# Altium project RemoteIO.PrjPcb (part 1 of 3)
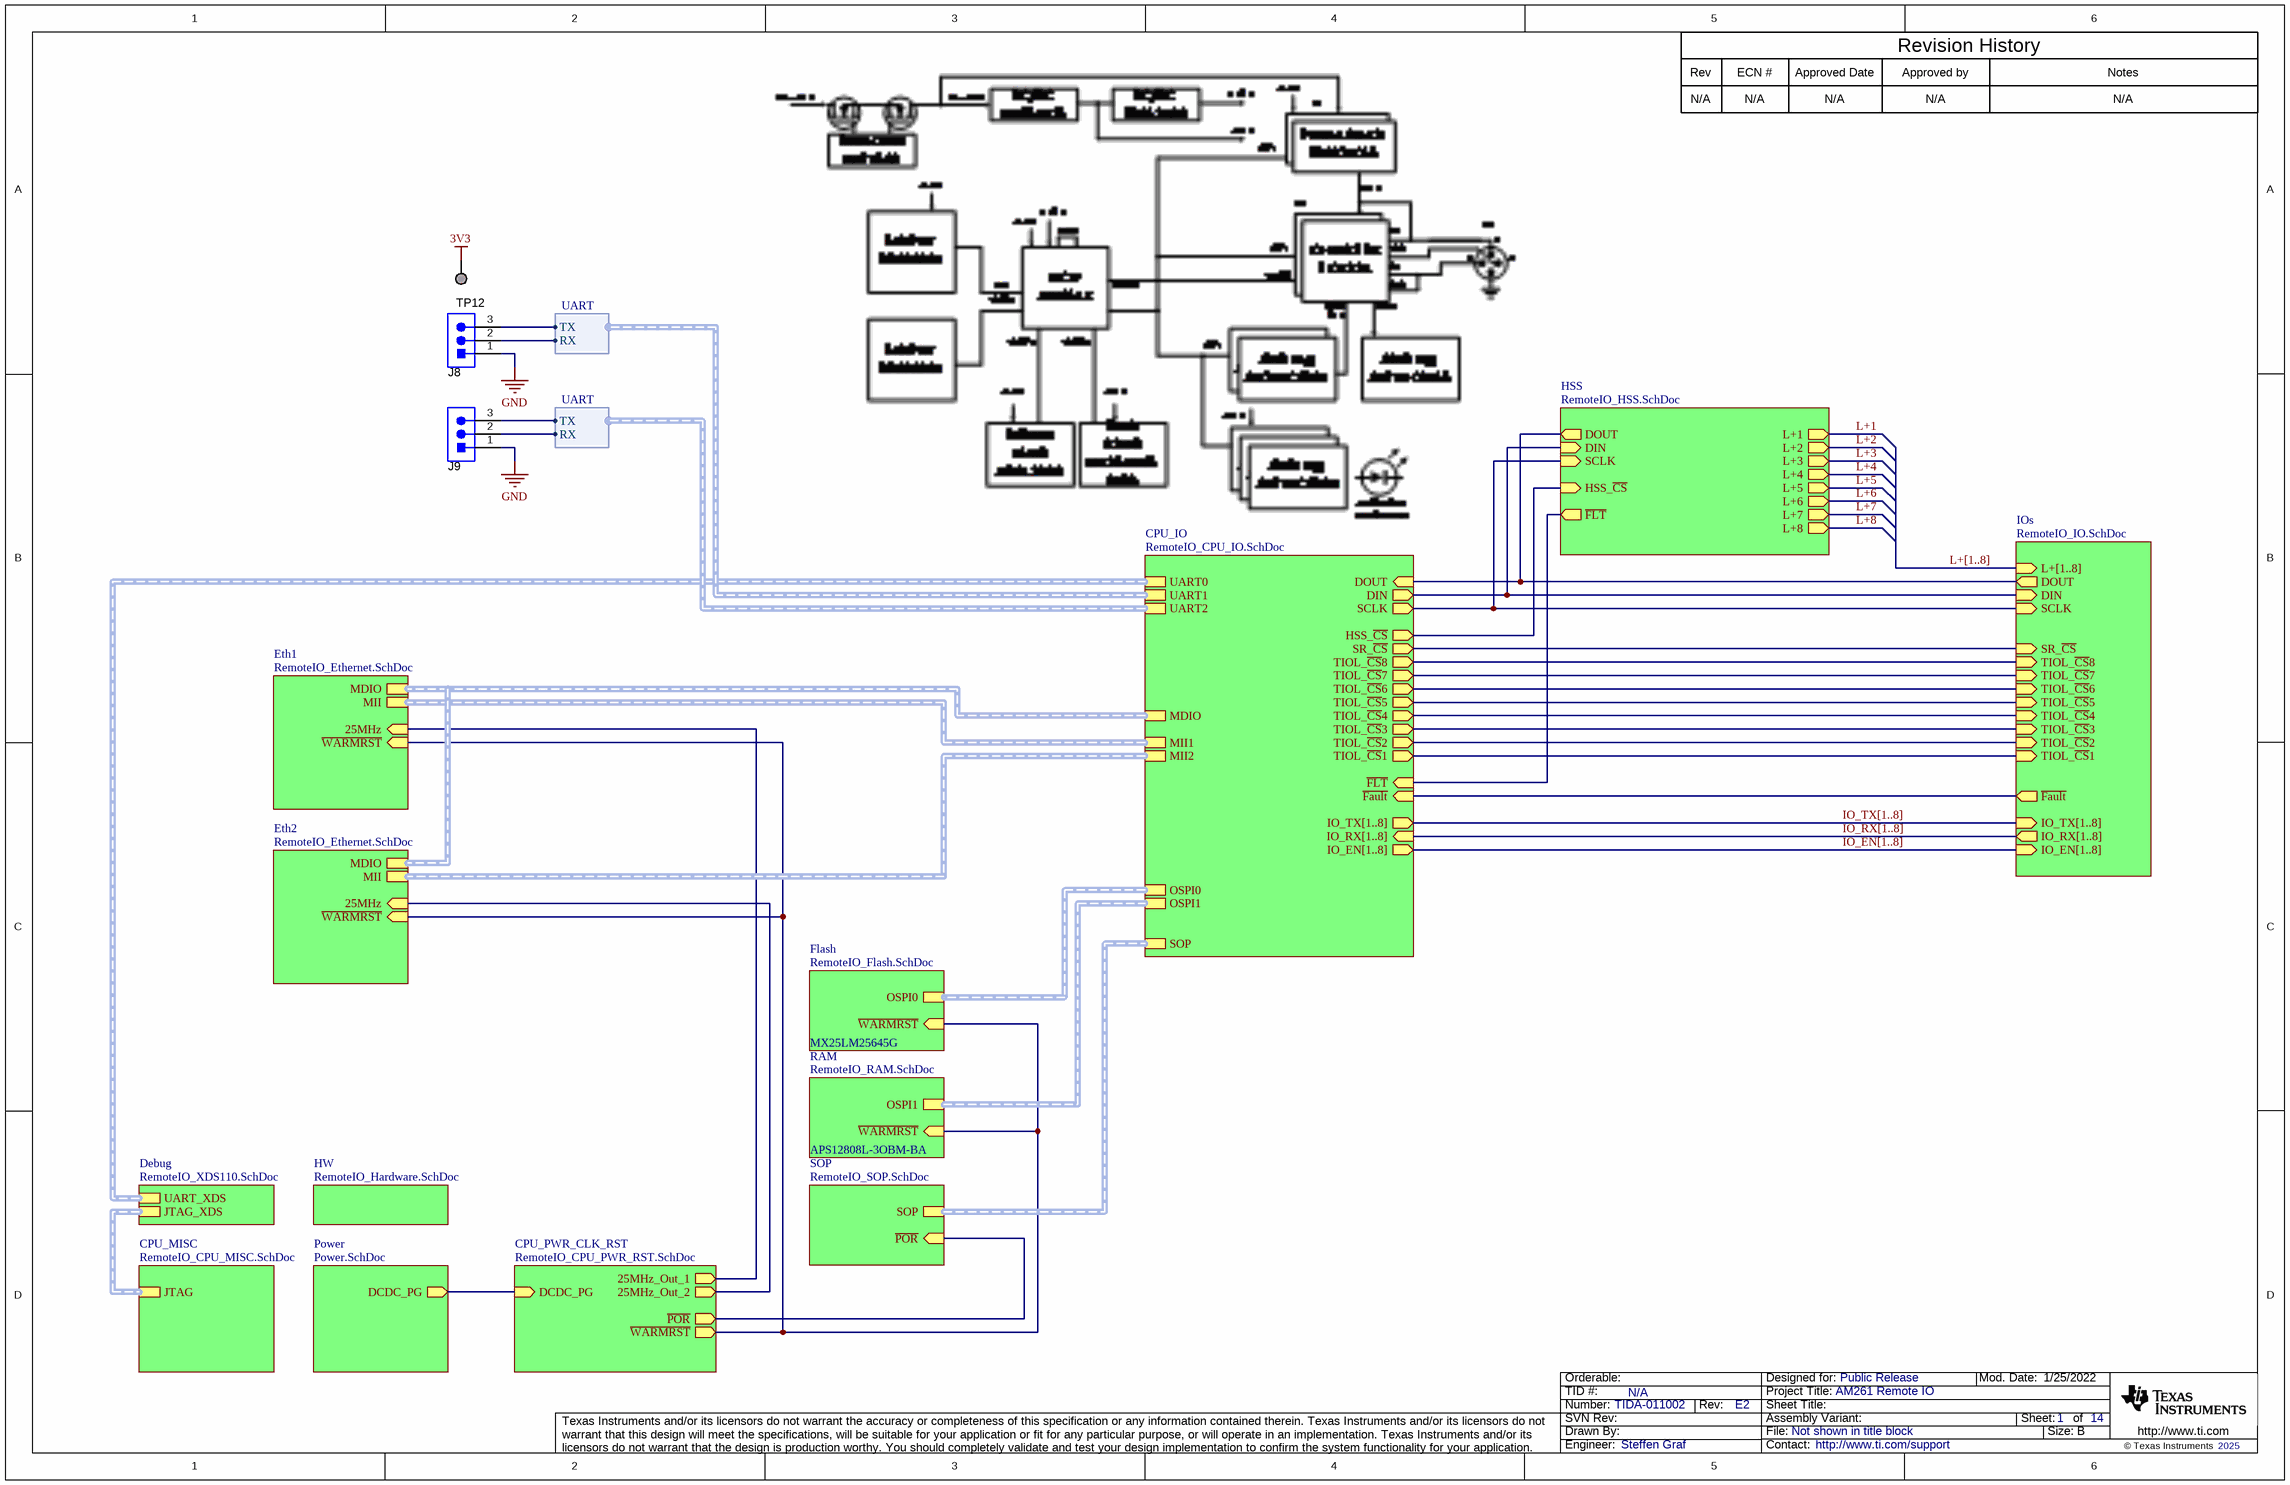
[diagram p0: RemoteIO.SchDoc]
TID: N/A; TechSupport: http://www.ti.com/support; SCH_Rev: E2; PRJ_Title: AM261 Remote IO; PRJ_Number: TIDA-011002; PRJ_Engineer: Steffen Graf; PRJ_Customer: Public Release; PCB_Rev: E2; PCB_Layout: Steffen Graf; CopyrightYear: 2025
14 sheets, 687 parts. Net scope: hierarchical (ports join the sheet entries above them; power ports are global).
Board file: RemoteIO.PcbDoc
Sheets:
  RemoteIO.SchDoc
    Power = Power.SchDoc
    Eth1 = RemoteIO_Ethernet.SchDoc
    Eth2 = RemoteIO_Ethernet.SchDoc
    CPU_IO = RemoteIO_CPU_IO.SchDoc
    IOs = RemoteIO_IO.SchDoc
      IO1 = RemoteIO_IOLinkPort.SchDoc
      IO2 = RemoteIO_IOLinkPort.SchDoc
      IO3 = RemoteIO_IOLinkPort.SchDoc
      IO4 = RemoteIO_IOLinkPort.SchDoc
      IO5 = RemoteIO_IOLinkPort.SchDoc
      IO6 = RemoteIO_IOLinkPort.SchDoc
      IO7 = RemoteIO_IOLinkPort.SchDoc
      IO8 = RemoteIO_IOLinkPort.SchDoc
    HW = RemoteIO_Hardware.SchDoc
    HSS = RemoteIO_HSS.SchDoc
    Flash = RemoteIO_Flash.SchDoc
    RAM = RemoteIO_RAM.SchDoc
    SOP = RemoteIO_SOP.SchDoc
    CPU_PWR_CLK_RST = RemoteIO_CPU_PWR_RST.SchDoc
    CPU_MISC = RemoteIO_CPU_MISC.SchDoc
    Debug = RemoteIO_XDS110.SchDoc

## Sheet RemoteIO.SchDoc
size 431 x 279 mm; Date: Not shown in title block; ApprovedBy: Not shown in title block; CheckedBy: Not shown in title block; Author: Not shown in title block; CompanyName: Not shown in title block; Engineer: Not shown in title block; Organization: Not shown in title block; Address1: Not shown in title block; Address2: Not shown in title block; Address3: Not shown in title block; Address4: Not shown in title block; DocumentNumber: 1; Revision: Use project parameter SCH_Rev; SheetNumber: 1; SheetTotal: 14; PageSetup: Record=PageOptions¦CenterHorizontal=True¦CenterVertical=True¦PrintScale=1.00¦XCorrection=1.00¦YCorrection=1.00¦PrintKind=0¦BorderSize=5000000¦LeftOffset=0¦BottomOffset=0¦Orientation=2¦PaperLength=1000¦PaperWidth=1000¦Scale=100¦PaperSource=15¦PrintQuality=600¦MediaType=1¦DitherType=10¦PaperKind=Letter¦PrintScaleMode=1

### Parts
J8  61300311121  [WURTH_61300311121]  (value not drawn)
J9  61300311121  [WURTH_61300311121]  (value not drawn)
TP12  TESTPOINT  [TP_50MIL-25MILHOLE]  (value not drawn)  (no BOM)

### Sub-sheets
CPU_IO = RemoteIO_CPU_IO.SchDoc: DOUT (in), DIN (out), SCLK (out), HSS_~{CS} (out), SR_~{CS} (out), TIOL_~{CS}8 (out), TIOL_~{CS}7 (out), TIOL_~{CS}6 (out), TIOL_~{CS}5 (out), TIOL_~{CS}4 (out), TIOL_~{CS}3 (out), TIOL_~{CS}2 (out), TIOL_~{CS}1 (out), ~{FLT} (in), ~{Fault} (in), IO_TX[1..8] (out), IO_RX[1..8] (in), IO_EN[1..8] (out), MII1 (harness MII), MII2 (harness MII), MDIO (harness MDIO), UART0 (harness UART), UART1 (harness UART), OSPI0 (harness OSPI), OSPI1 (harness OSPI), SOP (harness SOP), UART2 (harness UART)
CPU_MISC = RemoteIO_CPU_MISC.SchDoc: JTAG (harness JTAG)
CPU_PWR_CLK_RST = RemoteIO_CPU_PWR_RST.SchDoc: DCDC_PG (in), ~{POR} (out), ~{WARMRST} (out), 25MHz_Out_1 (out), 25MHz_Out_2 (out)
Debug = RemoteIO_XDS110.SchDoc: JTAG_XDS (harness JTAG), UART_XDS (harness UART)
Eth1 = RemoteIO_Ethernet.SchDoc: MII, MDIO, 25MHz (in), ~{WARMRST} (in)
Eth2 = RemoteIO_Ethernet.SchDoc: MII, MDIO, 25MHz (in), ~{WARMRST} (in)
Flash = RemoteIO_Flash.SchDoc: OSPI0 (harness OSPI), ~{WARMRST} (in)
HSS = RemoteIO_HSS.SchDoc: L+1 (out), L+2 (out), L+3 (out), L+4 (out), L+5 (out), L+6 (out), L+7 (out), L+8 (out), HSS_~{CS} (in), SCLK (in), DIN (in), DOUT (out), ~{FLT} (out)
HW = RemoteIO_Hardware.SchDoc: no entries
IOs = RemoteIO_IO.SchDoc: SR_~{CS} (in), ~{Fault} (out), TIOL_~{CS}8 (in), TIOL_~{CS}7 (in), TIOL_~{CS}6 (in), TIOL_~{CS}5 (in), TIOL_~{CS}4 (in), TIOL_~{CS}3 (in), TIOL_~{CS}2 (in), TIOL_~{CS}1 (in), SCLK (in), DIN (in), DOUT (out), L+[1..8] (in), IO_RX[1..8] (out), IO_TX[1..8] (in), IO_EN[1..8] (in)
Power = Power.SchDoc: DCDC_PG (out)
RAM = RemoteIO_RAM.SchDoc: OSPI1, ~{WARMRST} (in)
SOP = RemoteIO_SOP.SchDoc: SOP (harness SOP), ~{POR} (in)

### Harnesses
UART: TX, RX

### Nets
3V3: TP12.1
GND: J8.1 J9.1
25MHz: sheet Eth1/25MHz, sheet CPU_PWR_CLK_RST/25MHz_Out_1
25MHz: sheet Eth2/25MHz, sheet CPU_PWR_CLK_RST/25MHz_Out_2  [a separate net that carries the same name]
~{Fault}: sheet CPU_IO/~{Fault}, sheet IOs/~{Fault}
~{FLT}: sheet CPU_IO/~{FLT}, sheet HSS/~{FLT}
~{POR}: sheet SOP/~{POR}, sheet CPU_PWR_CLK_RST/~{POR}
~{WARMRST}: sheet Eth1/~{WARMRST}, sheet Eth2/~{WARMRST}, sheet Flash/~{WARMRST}, sheet RAM/~{WARMRST}, sheet CPU_PWR_CLK_RST/~{WARMRST}
CS1: sheet CPU_IO/TIOL_~{CS}1, sheet IOs/TIOL_~{CS}1
CS2: sheet CPU_IO/TIOL_~{CS}2, sheet IOs/TIOL_~{CS}2
CS3: sheet CPU_IO/TIOL_~{CS}3, sheet IOs/TIOL_~{CS}3
CS4: sheet CPU_IO/TIOL_~{CS}4, sheet IOs/TIOL_~{CS}4
CS5: sheet CPU_IO/TIOL_~{CS}5, sheet IOs/TIOL_~{CS}5
CS6: sheet CPU_IO/TIOL_~{CS}6, sheet IOs/TIOL_~{CS}6
CS7: sheet CPU_IO/TIOL_~{CS}7, sheet IOs/TIOL_~{CS}7
CS8: sheet CPU_IO/TIOL_~{CS}8, sheet IOs/TIOL_~{CS}8
DCDC_PG: sheet Power/DCDC_PG, sheet CPU_PWR_CLK_RST/DCDC_PG
DIN: sheet CPU_IO/DIN, sheet IOs/DIN, sheet HSS/DIN
DOUT: sheet CPU_IO/DOUT, sheet IOs/DOUT, sheet HSS/DOUT
HSS_~{CS}: sheet CPU_IO/HSS_~{CS}, sheet HSS/HSS_~{CS}
SCLK: sheet CPU_IO/SCLK, sheet IOs/SCLK, sheet HSS/SCLK
SR_~{CS}: sheet CPU_IO/SR_~{CS}, sheet IOs/SR_~{CS}
UART1_RX: J8.2 ; sheet CPU_IO/UART1.RX
UART1_TX: J8.3 ; sheet CPU_IO/UART1.TX
NetJ9_2: J9.2 ; sheet CPU_IO/UART2.RX
NetJ9_3: J9.3 ; sheet CPU_IO/UART2.TX

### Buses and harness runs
bus IO_EN[1..8] = sheet CPU_IO/IO_EN[1..8] = sheet IOs/IO_EN[1..8]
bus IO_RX[1..8] = sheet CPU_IO/IO_RX[1..8] = sheet IOs/IO_RX[1..8]
bus IO_TX[1..8] = sheet CPU_IO/IO_TX[1..8] = sheet IOs/IO_TX[1..8]
bus L+[1..8] = sheet IOs/L+[1..8]
harness sheet CPU_IO/MDIO = sheet Eth1/MDIO = sheet Eth2/MDIO
harness sheet CPU_IO/MII1 = sheet Eth1/MII
harness sheet CPU_IO/MII2 = sheet Eth2/MII
harness sheet CPU_IO/OSPI0 = sheet Flash/OSPI0
harness sheet CPU_IO/OSPI1 = sheet RAM/OSPI1
harness sheet CPU_IO/SOP = sheet SOP/SOP
harness sheet CPU_IO/UART0 = sheet Debug/UART_XDS
harness sheet CPU_MISC/JTAG = sheet Debug/JTAG_XDS

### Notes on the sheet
- Rev
- N/A
- ECN #
- Approved Date
- Approved by
- Revision History
- Notes
- MX25LM25645G
- APS12808L-3OBM-BA

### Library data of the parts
J8 J9 = CMP-0054796-4: Header, 2.54 mm, 3x1, Gold, TH; Manufacturer: Wurth Elektronik; Green_REACh: Passed; CT: FALSE; CNHeader: TRUE; Green_Lifecycle: Active
TP12 = CMP-0078143-4: TEST POINT.  No entry in BOM.

## Sheet Power.SchDoc
size 431 x 279 mm; Date: Not shown in title block; ApprovedBy: Not shown in title block; CheckedBy: Not shown in title block; Author: Not shown in title block; CompanyName: Not shown in title block; Engineer: Not shown in title block; Organization: Not shown in title block; Address1: Not shown in title block; Address2: Not shown in title block; Address3: Not shown in title block; Address4: Not shown in title block; DocumentNumber: 2; Revision: Use project parameter SCH_Rev; SheetNumber: 2; SheetTotal: 14; PageSetup: Record=PageOptions¦CenterHorizontal=True¦CenterVertical=True¦PrintScale=1.00¦XCorrection=1.00¦YCorrection=1.00¦PrintKind=0¦BorderSize=5000000¦LeftOffset=0¦BottomOffset=0¦Orientation=2¦PaperLength=1000¦PaperWidth=1000¦Scale=100¦PaperSource=15¦PrintQuality=600¦MediaType=1¦DitherType=10¦PaperKind=Letter¦PrintScaleMode=1
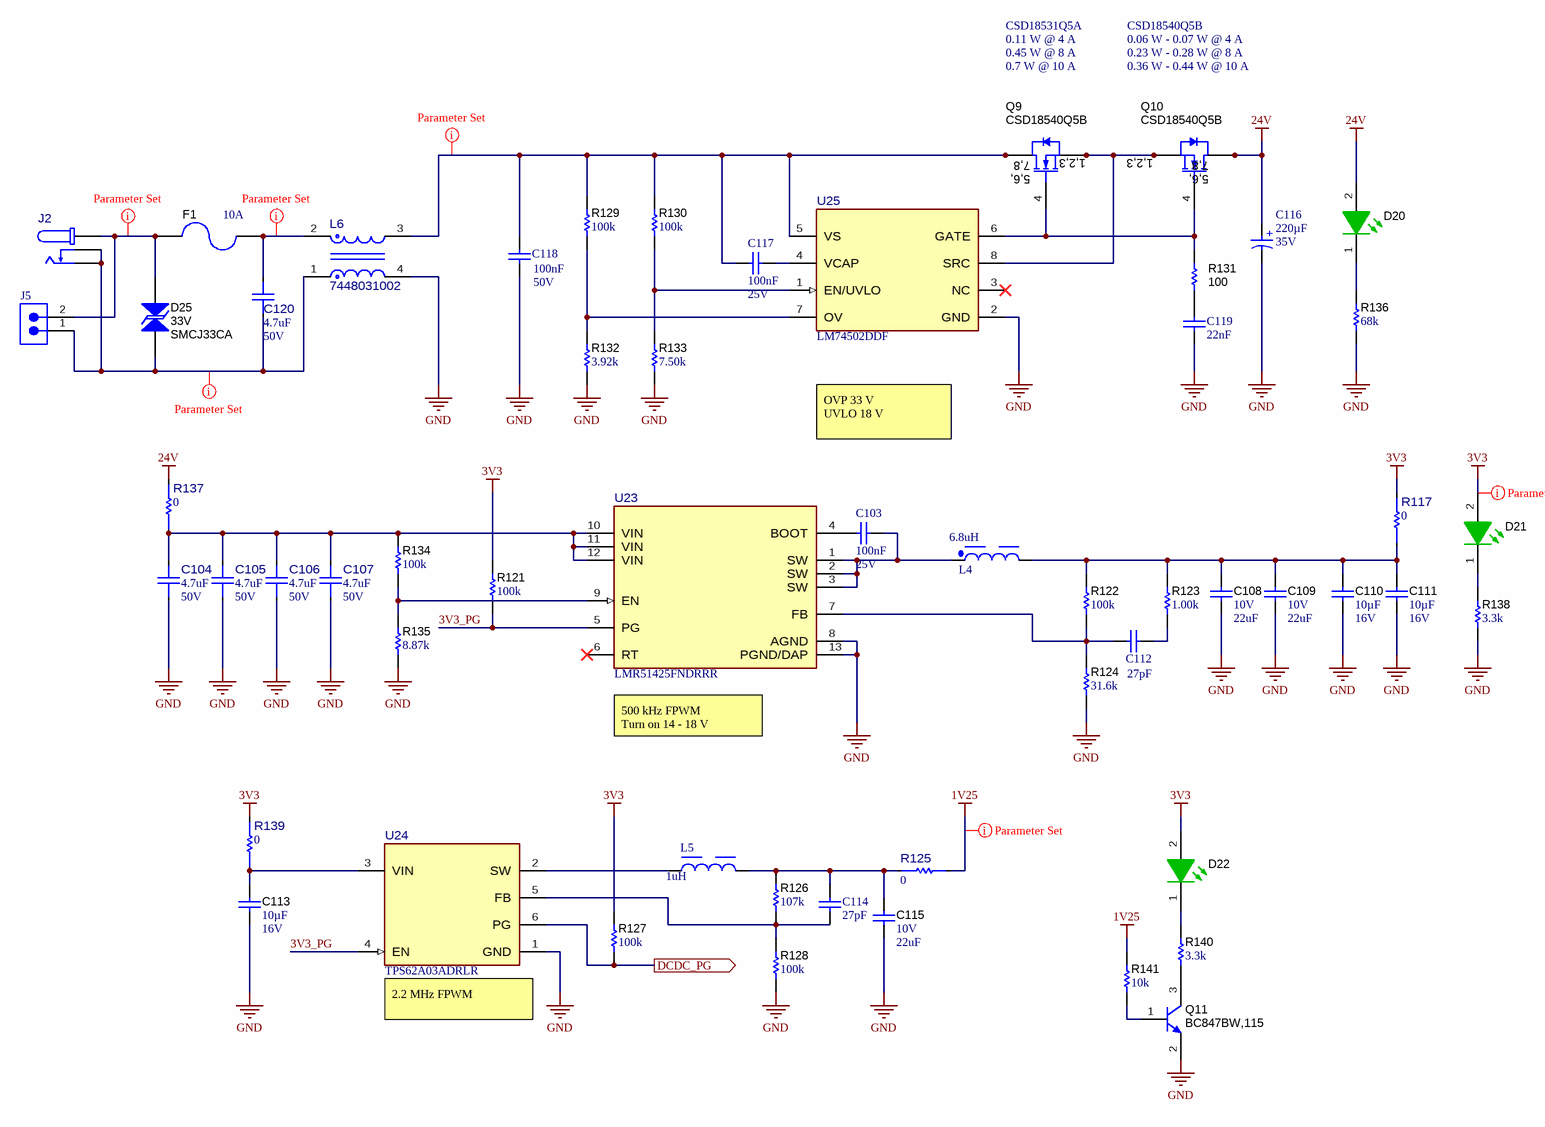
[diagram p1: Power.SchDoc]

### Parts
C103  Cap_F: 100nF  Rated Voltage (DC): 25V  [WCAP-CSGP_0402_L1W0.5H0.5]  (hidden comment: 885012105018)
C104  ValueDisplayed: 4.7uF  VDC_V: 50V  [FP-885012209048_1210-MFG]  (hidden comment: 885012209048)
C105  ValueDisplayed: 4.7uF  VDC_V: 50V  [FP-885012209048_1210-MFG]  (hidden comment: 885012209048)
C106  ValueDisplayed: 4.7uF  VDC_V: 50V  [FP-885012209048_1210-MFG]  (hidden comment: 885012209048)
C107  ValueDisplayed: 4.7uF  VDC_V: 50V  [FP-885012209048_1210-MFG]  (hidden comment: 885012209048)
C108  VDC_V: 10V  ValueDisplayed: 22uF  [1206_190]  (hidden comment: 885012208019)
C109  VDC_V: 10V  ValueDisplayed: 22uF  [1206_190]  (hidden comment: 885012208019)
C110  ValueDisplayed: 10µF  VDC_V: 16V  [1206]  (hidden comment: 885012208041)
C111  ValueDisplayed: 10µF  VDC_V: 16V  [1206]  (hidden comment: 885012208041)
C112  Cap_F: 27pF  [WCAP-CSRF_0402_L1W0.5H0.5]  (hidden comment: 885392005116)
C113  ValueDisplayed: 10µF  VDC_V: 16V  [1206]  (hidden comment: 885012208041)
C114  Cap_F: 27pF  [WCAP-CSRF_0402_L1W0.5H0.5]  (hidden comment: 885392005116)
C115  VDC_V: 10V  ValueDisplayed: 22uF  [1206_190]  (hidden comment: 885012208019)
C116  Cap_F: 220µF  Rated Voltage (DC): 35V  [WCAP-AS5H_D10H10.5]  (hidden comment: 865230557007)
C117  Cap_F: 100nF  Rated Voltage (DC): 25V  [WCAP-CSGP_0402_L1W0.5H0.5]  (hidden comment: 885012105018)
C118  Cap_F: 100nF  Rated Voltage (DC): 50V  [WCAP-CSGP_1206_L3.2W1.6H0.8]  (hidden comment: 885012208087)
C119  Cap_F: 22nF  [WCAP-CSST_0603_L1.6W0.8H0.8_Reflow]  (hidden comment: 885382206003)
C120  ValueDisplayed: 4.7uF  VDC_V: 50V  [FP-885012209048_1210-MFG]  (hidden comment: 885012209048)
D20  150040GS73240  [WL-SMCC_0402_Green]  (value not drawn)
D21  150040GS73240  [WL-SMCC_0402_Green]  (value not drawn)
D22  150040GS73240  [WL-SMCC_0402_Green]  (value not drawn)
D25  SMCJ33CA  value 33V  [SMC_Bi]
F1  Irating_A: 10A  [FUSE_6125FF]  (hidden comment: TR2/6125FF10-R)
J2  694106301002  [FP-694106301002_CONN_PWR_JACK-MFG]  (value not drawn)
J5  691305540002  [691305540002]  (value not drawn)
L4  Inductance: 6.8uH  [WE-MAPI_5030]  (hidden comment: 74438367068)
L5  Inductance: 1uH  [WE-MAPI_3020]  (hidden comment: 74438336010)
L6  7448031002  [FP-7448031002_PTH4_23MM0_17MM0-MFG]
Q9  CSD18540Q5B  [DNK0008A]
Q10  CSD18540Q5B  [DNK0008A]
Q11  BC847BW,115  [SOT-323]
R117  value 0  [FP-CRCW04020000Z0EDC_0402-MFG]  (hidden comment: CRCW04020000Z0EDC)
R121  ValueDisplayed: 100k  [0402]  (hidden comment: RC0402FR-07100KL)
R122  ValueDisplayed: 100k  [0402]  (hidden comment: RC0402FR-07100KL)
R123  ValueDisplayed: 1.00k  [0402]  (hidden comment: CRCW04021K00FKED)
R124  ValueDisplayed: 31.6k  [0402]  (hidden comment: CRCW040231K6FKED)
R125  value 0  [FP-CRCW04020000Z0EDC_0402-MFG]  (hidden comment: CRCW04020000Z0EDC)
R126  ValueDisplayed: 107k  [0402]  (hidden comment: CRCW0402107KFKED)
R127  ValueDisplayed: 100k  [0402]  (hidden comment: RC0402FR-07100KL)
R128  ValueDisplayed: 100k  [0402]  (hidden comment: RC0402FR-07100KL)
R129  ValueDisplayed: 100k  [0402]  (hidden comment: RC0402FR-07100KL)
R130  ValueDisplayed: 100k  [0402]  (hidden comment: RC0402FR-07100KL)
R131  ValueDisplayed: 100  [0402]  (hidden comment: CRCW0402100RJNED)
R132  ValueDisplayed: 3.92k  [0402]  (hidden comment: CRCW04023K92FKED)
R133  ValueDisplayed: 7.50k  [0402]  (hidden comment: CRCW04027K50FKED)
R134  ValueDisplayed: 100k  [0402]  (hidden comment: RC0402FR-07100KL)
R135  ValueDisplayed: 8.87k  [0402]  (hidden comment: CRCW04028K87FKED)
R136  ValueDisplayed: 68k  [0402]  (hidden comment: CRCW040268K0JNED)
R137  value 0  [FP-CRCW04020000Z0EDC_0402-MFG]  (hidden comment: CRCW04020000Z0EDC)
R138  ValueDisplayed: 3.3k  [0402]  (hidden comment: CRCW04023K30JNED)
R139  value 0  [FP-CRCW04020000Z0EDC_0402-MFG]  (hidden comment: CRCW04020000Z0EDC)
R140  ValueDisplayed: 3.3k  [0402]  (hidden comment: CRCW04023K30JNED)
R141  ValueDisplayed: 10k  [0402]  (hidden comment: CRCW040210K0JNED)
U23  LMR51425FNDRRR  [DRR0012E-MFG]
U24  TPS62A03ADRLR  [DRL0006A-MFG]
U25  LM74502DDF  [DDF0008A-MFG]

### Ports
DCDC_PG (out)

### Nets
1V25: R125.2 R141.2
3V3: D21.2(A) D22.2(A) R117.2 R121.2 R127.2 R139.2
24V: C116.1(P) D20.2(A) Q10.5(D) Q10.6(D) Q10.7(D) Q10.8(D) Q10.9(D) R137.2
GND: C104.1 C105.1 C106.1 C107.1 C108.2 C109.2 C110.2 C111.2 C113.2 C115.2 C116.2(N) C118.1 C119.1 L6.4 Q11.2(E) R124.1 R128.1 R132.1 R133.1 R135.1 R136.1 R138.1 U23.8(AGND) U23.13(PGND/DAP) U24.1(GND) U25.2(GND)
3V3_PG: R121.1 U23.5(PG) U24.4(EN)
DCDC_PG: R127.1 U24.6(PG) ; port DCDC_PG
NetC103_1: C103.1 L4.1 U23.1(SW) U23.2(SW) U23.3(SW)
NetC103_2: C103.2 U23.4(BOOT)
NetC104_2: C104.2 C105.2 C106.2 C107.2 R134.2 R137.1 U23.10(VIN) U23.11(VIN) U23.12(VIN)
NetC108_1: C108.1 C109.1 C110.1 C111.1 L4.2 R117.1 R122.2 R123.2
NetC112_1: C112.1 R122.1 R124.2 U23.7(FB)
NetC112_2: C112.2 R123.1
NetC113_1: C113.1 R139.1 U24.3(VIN)
NetC114_1: C114.1 R126.1 R128.2 U24.5(FB)
NetC114_2: C114.2 C115.1 L5.2 R125.1 R126.2
NetC117_1: C117.1 U25.4(VCAP)
NetC117_2: C117.2 C118.2 L6.3 Q9.5(D) Q9.6(D) Q9.7(D) Q9.8(D) Q9.9(D) R129.2 R130.2 U25.5(VS)
NetC119_2: C119.2 R131.1
NetC120_1: C120.1 D25.1 J2.2 J2.3 J5.1 L6.1
NetC120_2: C120.2 F1.1 L6.2
NetD20_1: D20.1(K) R136.2
NetD21_1: D21.1(K) R138.2
NetD22_1: D22.1(K) R140.2
NetD25_2: D25.2 F1.2 J2.1 J5.2
NetL5_1: L5.1 U24.2(SW)
NetQ9_1: Q9.1(S) Q9.2(S) Q9.3(S) Q10.1(S) Q10.2(S) Q10.3(S) U25.8(SRC)
NetQ9_4: Q9.4(G) Q10.4(G) R131.2 U25.6(GATE)
NetQ11_1: Q11.1(B) R141.1
NetQ11_3: Q11.3(C) R140.1
NetR129_1: R129.1 R132.2 U25.7(OV)
NetR130_1: R130.1 R133.2 U25.1(EN/UVLO)
NetR134_1: R134.1 R135.2 U23.9(EN)

Not connected (* = marked no-connect by the designer): U23 6(RT)*; U25 3(NC)*

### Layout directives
net class PWR: NetC117_2, NetC120_1, NetC120_2, NetD25_2
rule Supply Nets [Voltage = 3.300]: 3V3
rule Supply Nets [Voltage = 1.250]: 1V25

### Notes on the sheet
- 0.11 W @ 4 A
- CSD18531Q5A
- 0.06 W - 0.07 W @ 4 A
- CSD18540Q5B
- 0.45 W @ 8 A
- 0.7 W @ 10 A
- 0.36 W - 0.44 W @ 10 A
- 0.23 W - 0.28 W @ 8 A
- OVP 33 V
  UVLO 18 V
- (near U23) 500 kHz FPWM
  Turn on 14 - 18 V
- (near U24) 2.2 MHz FPWM

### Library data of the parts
C103 C117 = CMP-0119143-1: WCAP-CSGP Multilayer Ceramic Chip Capacitor, General Purpose, size 0402, X5R, 100nF, 25VDC; Manufacturer: Wurth Elektronik; PartNumber: '885012105018; Capacitance Tolerance: +/-20%; Case/Size Code: 0402; Dissipation Factor: 10%; Insulation Resistance: 5GOhm; Technical Reference: X5R0402104M025DFCT10000
C104-C107 C120 = CMP-0096739-1: 4.7 µF ±10% 50V Ceramic Capacitor X7R 1210 (3225 Metric); Manufacturer: Wurth; TempCo: 15%; Cap_F: 4.7µF; AEC Qualified: No; SizeZ_mm: 2.7mm; Value: 4.7µF
C108 C109 C115 = CMP-0064937-2: CAP, CERM, 22 uF, 10 V,+/- 10%, X7R, 1206; Manufacturer: Wurth Elektronik; TaMin_C: -55°C; Polarized: N; SizeAreaWB_mm2: 10.92; Value1: Unknown; U/M: EA; Value: 22uF; TaMax_C: 125°C; SizeZ_mm: 1.9; SizeX_mm: 3.2; SizeY_mm: 1.6; Cap_Case: 1206; SizeArea_mm2: 5.12; Cap_F: 22µF; AEC Category: Q200
C110 C111 C113 = CMP-0750070-1: CAP, CERM, 10 µF, 16 V,+/- 10%, X7R, 1206; Manufacturer: Wurth Elektronik; SizeArea_mm2: 5.12; SizeZ_mm: 1.35; Polarized: N; SizeAreaWB_mm2: 10.92; AEC Category: Q200; SizeX_mm: 3.2; TaMin_C: -55°C; U/M: EA; TaMax_C: 125°C; Value: 10uF; SizeY_mm: 1.6
C112 C114 = CMP-0112443-1: WCAP-CSRF Multilayer Ceramic Chip Capacitor, High Frequency, size 0402, NP0 Class I, 27pF, 50VDC; Manufacturer: Wurth Elektronik; Capacitance Tolerance: +/-5%; Case/Size Code: 0402; Insulation Resistance: 10GOhm; Q Factor: 940; Rated Voltage (DC): 50V; Technical Reference: NP00402270J050DFCT1R000
C116 = CMP-0114361-1: WCAP-AS5H Aluminum Electrolytic Capacitor, V-Chip, D10 x H10.5mm, 220µF, 35V; Manufacturer: Wurth Elektronik; Capacitance Tolerance: +/-20%; Dissipation Factor: 13%; Endurance: 5000h; Leakage Current: 77uA; Ripple Current: 280mA; Technical Reference: ASDF105221M035DVCTEE000
C118 = CMP-0119630-1: WCAP-CSGP Multilayer Ceramic Chip Capacitor, General Purpose, size 1206, X7R, 100nF, 50VDC; Manufacturer: Wurth Elektronik; Capacitance Tolerance: +/-10%; Case/Size Code: 1206; Dissipation Factor: 2.5%; Insulation Resistance: 5GOhm; Technical Reference: X7R1206104K050DFCT10000
C119 = CMP-0119892-1: WCAP-CSST Multilayer Ceramic Chip Capacitor, Soft Termination, size 0603, X7R Class II, 22nF, 50VDC; Manufacturer: Wurth Elektronik; Capacitance Tolerance: +/-10%; Case/Size Code: 0603; Dissipation Factor: 2.5%; Insulation Resistance: 10GOhm; Rated Voltage (DC): 50V; Technical Reference: X7R0603223K050DFCT1S000
D20-D22 = CMP-0081765-2: LED, Green, SMD; Manufacturer: Wurth Elektronik; Vr_V: 5V; Io_A: 20mA; Tjmax_C: 95°C; Ir_A: 10µA; Power_TotalModule: 99mW; Value2: 3.2V; SizeArea_mm2: 0.5; SizeX_mm: 1; Value1: 0.099W; Angle: 120; Type: InGaN; SizeAreaWB_mm2: 3
D25 = CMP-0005695-3: Diode, TVS, Bi, 33 V, SMC; Manufacturer: Bourns; SizeZ_mm: 2.6; Ppk: 1.5kW; Value1: 1500W; AEC Category: Q101; SizeArea_mm2: 50.5686; SizeX_mm: 8.13; SizeAreaWB_mm2: 83.2686; SizeY_mm: 6.22
F1 = CMP-0003609-2: Fuse, 10 A, 125 VAC, 72 VDC, SMD; Manufacturer: Eaton; VAC_V: 125V; VDC_V: 72V; Rtyp_Ohm: 7.3m; MeltingTyp: 67.75; Value: 10A
J2 = CMP-0127094-1: Power Barrel Connector Jack 2.10mm ID (0.083"), 5.50mm OD (0.217") Through Hole, Right Angle; Manufacturer: Wurth; ContactFinish: Gold,Tin; Current_A: 5A; Voltage_V: 30V; AEC Qualified: No; Conn Gender: Male; SizeZ_mm: 11mm
J5 = 691305540002: WR-TBL Series 3055 PCB Header Horizontal Entry with Plastic Latches, THT, pitch 5.08mm, 02p; Manufacturer: Wurth Elektronik; Modularity: No; Rated Current: 16A; System: Pluggable Connector; Working Voltage: 300V
L4 = CMP-0099177-1: WE-MAPI SMT Power Inductor, size 5030, 6.8uH, 4.3A, 48.3mOhm; Manufacturer: Wurth Elektronik; Case/Size Code: 5030; DC Resistance: 42mOhm; Saturation Current: 5.7A; Self Resonant Frequency: 15.5MHz; Value: 6.8 µH
L5 = CMP-0099114-2: WE-MAPI SMT Power Inductor, size 3020, 1uH, 4A, 32mOhm; Manufacturer: Wurth Elektronik; Case/Size Code: 3020; DC Resistance: 26mOhm; Saturation Current: 5A; Self Resonant Frequency: 67MHz; Value: 1 µH
L6 = CMP-0098028-1: 2 mH @ 10 kHz 2 Line Common Mode Choke Through Hole 10A DCR 6mOhm; Manufacturer: Wurth Electronics; SizeZ_mm: 25mm; Tolerance_%: 50%; AEC Qualified: No; Test Frequency: 10kHz; Ind_H: 2mH; DCR_ohm: 6m
Q9 Q10 = CMP-0000823-2: MOSFET, N-CH, 60 V, 100 A, DNK0008A (VSON-CLIP-8); Alternate Manufacturer: None; Manufacturer: Texas Instruments; SizeZ_mm: 1; ChType: N; Value2: 41 nC; Value1: 0.003; VdsMax_V: 60V; SizeX_mm: 6; SizeY_mm: 5; Vgs_V: 20V; Value: 60V; Rdson45_ohm: 3.3m; SizeArea_mm2: 30; AEC Category: Q101; IdsMax_A: 100A; SizeAreaWB_mm2: 56; U/M: EA; QgTyp_nC: 41
Q11 = CMP-0000486-2: Transistor, NPN, 45 V, 0.1 A, AEC-Q101, SOT-323; Manufacturer: NXP Semiconductor; TaMax_C: 150°C; Value2: 800; Value1: 0.1 A; Vcesat1_V: 90mV; SizeX_mm: 2.2; TaMin_C: -65°C; IcRated_A: 100mA; CompType: BJT; SizeZ_mm: 1.1; AEC Qualified: Y; Value: 45 V; SizeArea_mm2: 4.84; NPN: 1; Vceo_V: 45V; PNP: 0; AEC Category: Q101; SizeAreaWB_mm2: 10.24; U/M: EA
R117 R125 R137 R139 = CMP-0093210-1: Jumper 0.063W, 1/16W Chip Resistor 0402 (1005 Metric) - Thick Film; Manufacturer: Vishay; AEC Qualified: No; VDC_V: 50V; Power_W: 63mW; SizeZ_mm: 0.35mm
R121 R122 R127-R130 R134 = CMP-0026721-1: RES, 100 k, 1%, 0.0625 W, 0402; Manufacturer: Yageo America; Power_W: 62.5mW; TempCo: 100 ppm/C; U/M: EA; Value: 100k; EIA_Code: E96; SizeX_mm: 1; SizeY_mm: 0.5; SizeZ_mm: 0.6; AEC Qualified: N; VDC_V: 50V; AEC Category: Q200
R123 = CMP-0026071-3: RES, 1.00 k, 1%, 0.063 W, AEC-Q200 Grade 0, 0402; Manufacturer: Vishay-Dale; Power_W: 63mW; TempCo: 100 ppm/C; Value_Code: 1k00; Value: 1.00k; EIA_Code: E96; Res_ohm: 1k; SizeX_mm: 1; SizeY_mm: 0.5; SizeZ_mm: 0.6; Value2: 0.063W; AEC Qualified: Y; VDC_V: 50V; AEC Category: Q200; AEC Grade: 0
R124 = CMP-0026290-2: RES, 31.6 k, 1%, 0.063 W, AEC-Q200 Grade 0, 0402; Manufacturer: Vishay-Dale; Power_W: 63mW; TempCo: 100 ppm/C; Value_Code: 31k6; Value: 31.6k; EIA_Code: E96; SizeX_mm: 1; SizeY_mm: 0.5; SizeZ_mm: 0.6; Value2: 0.063W; AEC Qualified: Y; VDC_V: 50V; AEC Category: Q200; AEC Grade: 0
R126 = CMP-0025956-3: RES, 107 k, 1%, 0.063 W, AEC-Q200 Grade 0, 0402; Manufacturer: Vishay-Dale; Power_W: 63mW; TempCo: 100 ppm/C; Value: 107k; EIA_Code: E96; SizeX_mm: 1; SizeY_mm: 0.5; SizeZ_mm: 0.6; Value2: 0.063W; AEC Qualified: Y; VDC_V: 50V; AEC Category: Q200; AEC Grade: 0
R131 = CMP-0026824-3: RES, 100, 5%, 0.063 W, AEC-Q200 Grade 0, 0402; Manufacturer: Vishay-Dale; Value: 100; Value_Code: 100R; Power_W: 63mW; Value2: 0.063W; VDC_V: 50V; TempCo: 200 ppm/C; SizeArea_mm2: 0.5; SizeX_mm: 1; SizeZ_mm: 0.6; EIA_Code: E24; AEC Category: Q200; AEC Qualified: Y; AEC Grade: 0
R132 = CMP-0026340-2: RES, 3.92 k, 1%, 0.063 W, AEC-Q200 Grade 0, 0402; Manufacturer: Vishay-Dale; Power_W: 63mW; TempCo: 100 ppm/C; Value_Code: 3k92; Value: 3.92k; EIA_Code: E96; SizeX_mm: 1; SizeY_mm: 0.5; SizeZ_mm: 0.6; Value2: 0.063W; AEC Qualified: Y; VDC_V: 50V; AEC Category: Q200; AEC Grade: 0
R133 = CMP-0026555-2: RES, 7.50 k, 1%, 0.063 W, AEC-Q200 Grade 0, 0402; Manufacturer: Vishay-Dale; Power_W: 63mW; TempCo: 100 ppm/C; Value_Code: 7k50; Value: 7.50k; EIA_Code: E96; Res_ohm: 7.5k; SizeX_mm: 1; SizeY_mm: 0.5; SizeZ_mm: 0.6; Value2: 0.063W; AEC Qualified: Y; VDC_V: 50V; AEC Category: Q200; AEC Grade: 0
R135 = CMP-0026592-2: RES, 8.87 k, 1%, 0.063 W, AEC-Q200 Grade 0, 0402; Manufacturer: Vishay-Dale; Power_W: 63mW; TempCo: 100 ppm/C; Value_Code: 8k87; Value: 8.87k; EIA_Code: E96; SizeX_mm: 1; SizeY_mm: 0.5; SizeZ_mm: 0.6; Value2: 0.063W; AEC Qualified: Y; VDC_V: 50V; AEC Category: Q200; AEC Grade: 0
R136 = CMP-0026963-3: RES, 68 k, 5%, 0.063 W, AEC-Q200 Grade 0, 0402; Manufacturer: Vishay-Dale; Power_W: 63mW; TempCo: 200 ppm/C; Value_Code: 68k0; Value: 68k; EIA_Code: E24; SizeX_mm: 1; SizeY_mm: 0.5; SizeZ_mm: 0.6; Value2: 0.063W; AEC Qualified: Y; VDC_V: 50V; AEC Category: Q200; AEC Grade: 0
R138 R140 = CMP-0026918-5: RES, 3.3 k, 5%, 0.063 W, AEC-Q200 Grade 0, 0402; Manufacturer: Vishay-Dale; Power_W: 63mW; TempCo: 200 ppm/C; Value_Code: 3k30; Value: 3.3k; EIA_Code: E24; SizeX_mm: 1; SizeY_mm: 0.5; SizeZ_mm: 0.6; Value2: 0.063W; AEC Qualified: Y; VDC_V: 50V; AEC Category: Q200; AEC Grade: 0
R141 = CMP-0026825-5: RES, 10 k, 5%, 0.063 W, AEC-Q200 Grade 0, 0402; Manufacturer: Vishay-Dale; Power_W: 63mW; TempCo: 200 ppm/C; Value_Code: 10k0; Value: 10k; EIA_Code: E24; SizeX_mm: 1; SizeY_mm: 0.5; SizeZ_mm: 0.6; Value2: 0.063W; AEC Qualified: Y; VDC_V: 50V; AEC Category: Q200; AEC Grade: 0
U23 = CMP-0096682-1: 4-V to 36-V, 5-A Synchronous Step-Down DC/DC Converter with Low IQ; Manufacturer: Texas Instruments; Min Supply Voltage: 4V; Max Supply Voltage: 36V; Output Voltage: 1-16V; Output Type: AdjustableProgrammable; Nominal Supply Current: 25uA; Standoff Height: 0mm; Max Duty Cycle: 97%; Number Of Outputs: 1; Switching Frequency: 200-1100kHz; AEC Qualified: No; Switching Topology: Buck; SizeZ_mm: 0.8mm; TJmax_C: +150°C
U24 = CMP-0121127-1: 3-A, High-Efficiency, Synchronous Buck Converter in a SOT563 Package; Manufacturer: Texas Instruments; SizeZ_mm: 0.6mm; AEC Qualified: No; Max Duty Cycle: 100%; Max Supply Voltage: 5.5V; Min Supply Voltage: 2.5V; Nominal Supply Current: 28.5uA; Number Of Outputs: 1; Output Type: AdjustableProgrammable; Output Voltage: 0.6-5.5V; Standoff Height: 0mm; Switching Frequency: 2.2MHz; TJmax_C: +125°C
U25 = CMP-0095525-1: Low IQ High Side Switch Controller With Reverse Polarity and Overvoltage Protection; Manufacturer: Texas Instruments; AEC Qualified: No; TaMin_C: -40°C; Standoff Height: 0mm; TJmax_C: +150°C; Max Supply Voltage: 60V; TaMax_C: +125°C; Nominal Supply Current: 45uA; Min Supply Voltage: 4V; Number Of Outputs: 1; SizeZ_mm: 1.1mm

## Sheet RemoteIO_Ethernet.SchDoc
size 431 x 279 mm; Date: Not shown in title block; ApprovedBy: Not shown in title block; CheckedBy: Not shown in title block; Author: Not shown in title block; CompanyName: Not shown in title block; Engineer: Not shown in title block; Organization: Not shown in title block; Address1: Not shown in title block; Address2: Not shown in title block; Address3: Not shown in title block; Address4: Not shown in title block; DocumentNumber: 11; Revision: Use project parameter SCH_Rev; SheetNumber: 11; SheetTotal: 14; PageSetup: Record=PageOptions¦CenterHorizontal=True¦CenterVertical=True¦PrintScale=1.00¦XCorrection=1.00¦YCorrection=1.00¦PrintKind=0¦BorderSize=5000000¦LeftOffset=0¦BottomOffset=0¦Orientation=2¦PaperLength=1000¦PaperWidth=1000¦Scale=100¦PaperSource=15¦PrintQuality=600¦MediaType=1¦DitherType=10¦PaperKind=Letter¦PrintScaleMode=1
Used 2 times, as channels Eth1, Eth2. Parts and nets are listed once, with the designators drawn on the sheet.
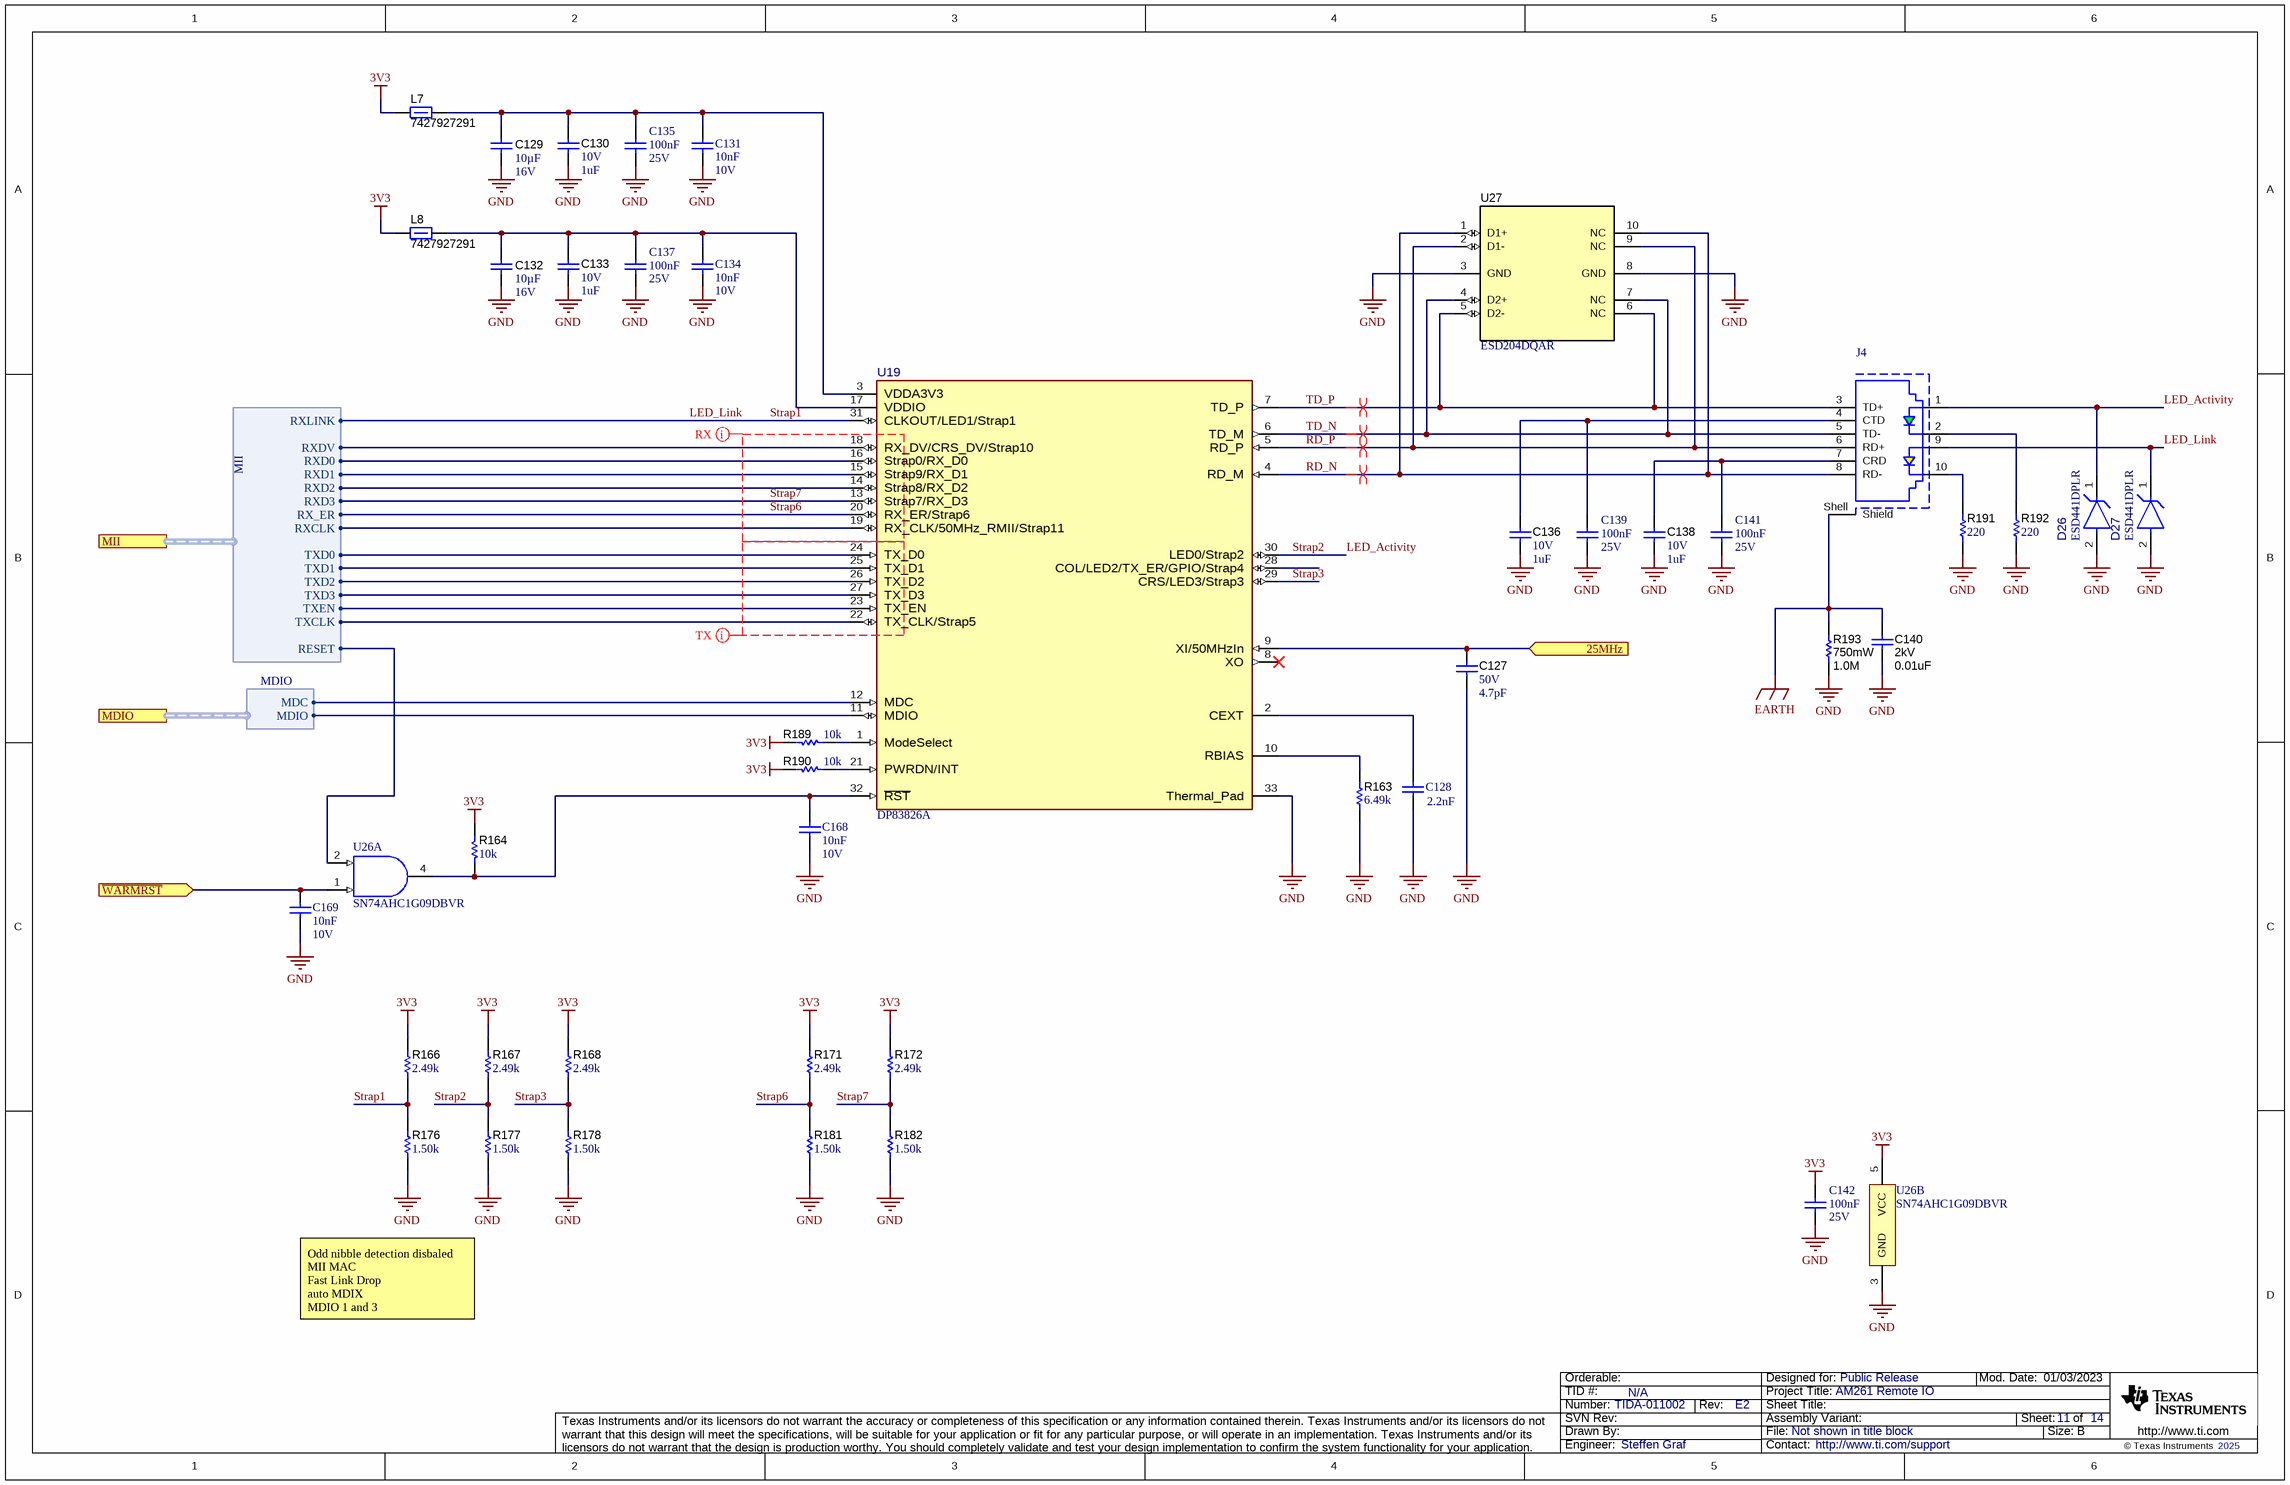
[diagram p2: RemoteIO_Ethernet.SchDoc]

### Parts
C127  VDC_V: 50V  ValueDisplayed: 4.7pF  [0402]  (hidden comment: GRM1555C1H4R7WA01D)
C128  Cap_F: 2.2nF  [WCAP-CSGP_0402_L1W0.5H0.5]  (hidden comment: 885012205063)
C129  ValueDisplayed: 10µF  VDC_V: 16V  [1206]  (hidden comment: 885012208041)
C130  VDC_V: 10V  ValueDisplayed: 1uF  [0402]  (hidden comment: 885012105012)
C131  Cap_F: 10nF  Rated Voltage (DC): 10V  [WCAP-CSGP_0402_L1W0.5H0.5]  (hidden comment: 885012205012)
C132  ValueDisplayed: 10µF  VDC_V: 16V  [1206]  (hidden comment: 885012208041)
C133  VDC_V: 10V  ValueDisplayed: 1uF  [0402]  (hidden comment: 885012105012)
C134  Cap_F: 10nF  Rated Voltage (DC): 10V  [WCAP-CSGP_0402_L1W0.5H0.5]  (hidden comment: 885012205012)
C135  Cap_F: 100nF  Rated Voltage (DC): 25V  [WCAP-CSGP_0402_L1W0.5H0.5]  (hidden comment: 885012105018)
C136  VDC_V: 10V  ValueDisplayed: 1uF  [0402]  (hidden comment: 885012105012)
C137  Cap_F: 100nF  Rated Voltage (DC): 25V  [WCAP-CSGP_0402_L1W0.5H0.5]  (hidden comment: 885012105018)
C138  VDC_V: 10V  ValueDisplayed: 1uF  [0402]  (hidden comment: 885012105012)
C139  Cap_F: 100nF  Rated Voltage (DC): 25V  [WCAP-CSGP_0402_L1W0.5H0.5]  (hidden comment: 885012105018)
C140  VDC_V: 2kV  ValueDisplayed: 0.01uF  [1825]  (hidden comment: 1825GC103KAT1A)
C141  Cap_F: 100nF  Rated Voltage (DC): 25V  [WCAP-CSGP_0402_L1W0.5H0.5]  (hidden comment: 885012105018)
C142  Cap_F: 100nF  Rated Voltage (DC): 25V  [WCAP-CSGP_0402_L1W0.5H0.5]  (hidden comment: 885012105018)
C168  Cap_F: 10nF  Rated Voltage (DC): 10V  [WCAP-CSGP_0402_L1W0.5H0.5]  (hidden comment: 885012205012)
C169  Cap_F: 10nF  Rated Voltage (DC): 10V  [WCAP-CSGP_0402_L1W0.5H0.5]  (hidden comment: 885012205012)
D26  ESD441DPLR  [DPL0002A-MFG]
D27  ESD441DPLR  [DPL0002A-MFG]
J4  7498011211  [7498011211]  (value not drawn)
L7  7427927291  [0402]
L8  7427927291  [0402]
R163  ValueDisplayed: 6.49k  [0402]  (hidden comment: CRCW04026K49FKED)
R164  ValueDisplayed: 10k  [0402]  (hidden comment: CRCW040210K0JNED)
R166  ValueDisplayed: 2.49k  [0402]  (hidden comment: CRCW04022K49FKED)
R167  ValueDisplayed: 2.49k  [0402]  (hidden comment: CRCW04022K49FKED)
R168  ValueDisplayed: 2.49k  [0402]  (hidden comment: CRCW04022K49FKED)
R171  ValueDisplayed: 2.49k  [0402]  (hidden comment: CRCW04022K49FKED)
R172  ValueDisplayed: 2.49k  [0402]  (hidden comment: CRCW04022K49FKED)
R176  ValueDisplayed: 1.50k  [0402]  (hidden comment: CRCW04021K50FKED)
R177  ValueDisplayed: 1.50k  [0402]  (hidden comment: CRCW04021K50FKED)
R178  ValueDisplayed: 1.50k  [0402]  (hidden comment: CRCW04021K50FKED)
R181  ValueDisplayed: 1.50k  [0402]  (hidden comment: CRCW04021K50FKED)
R182  ValueDisplayed: 1.50k  [0402]  (hidden comment: CRCW04021K50FKED)
R189  ValueDisplayed: 10k  [0402]  (hidden comment: CRCW040210K0JNED)
R190  ValueDisplayed: 10k  [0402]  (hidden comment: CRCW040210K0JNED)
R191  ValueDisplayed: 220  [0603]  (hidden comment: CRCW0603220RJNEA)
R192  ValueDisplayed: 220  [0603]  (hidden comment: CRCW0603220RJNEA)
R193  Power_W: 750mW  ValueDisplayed: 1.0M  [2010]  (hidden comment: CRCW20101M00JNEF)
U19  DP83826A  [RHB0032M-MFG]
U26  SN74AHC1G09DBVR  [DBV0005A_N]  (parts A,B of 2)
U27  ESD204DQAR  [DQA0010A]

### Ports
25MHz (in), MDIO (harness MDIO), MII (harness MII), ~{WARMRST} (in)

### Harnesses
MII: RXDV, RXD0, RXD1, RXD2, RXD3, RX_ER, RXCLK, RXLINK, TXD0, TXD1, TXD2, TXD3, TXEN, TXCLK, RESET
MDIO: MDC, MDIO

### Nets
3V3: C142.2 L7.2 L8.2 R164.2 R166.2 R167.2 R168.2 R171.2 R172.2 R189.2 R190.2 U26.5(VCC)
EARTH: C140.2 J4.Shell(Shield) R193.1
GND: C127.2 C128.1 C129.2 C130.2 C131.1 C132.2 C133.2 C134.1 C135.1 C136.2 C137.1 C138.2 C139.1 C140.1 C141.1 C142.1 C168.1 C169.1 D26.2(GND) D27.2(GND) R163.1 R176.1 R177.1 R178.1 R181.1 R182.1 R191.1 R192.1 R193.2 U19.33(Thermal_Pad) U26.3(GND) U27.3(GND) U27.8(GND)
25MHz: C127.1 U19.9(XI/50MHzIn) ; port 25MHz
~{WARMRST}: C169.2 U26.1(A) ; port ~{WARMRST}
LED_Activity: D26.1(IO) J4.1 R167.1 R177.2 U19.30(LED0/Strap2)  [also labelled Strap2]
LED_Link: D27.1(IO) J4.9 R166.1 R176.2 U19.31(CLKOUT/LED1/Strap1) ; port MII.RXLINK  [also labelled Strap1]
RD_N: J4.8(RD-) U19.4(RD_M) U27.1(D1+) U27.10(NC)
RD_P: J4.6(RD+) U19.5(RD_P) U27.2(D1-) U27.9(NC)
Strap3: R168.1 R178.2 U19.29(CRS/LED3/Strap3)
Strap6: R171.1 R181.2 U19.20(RX_ER/Strap6) ; port MII.RX_ER
Strap7: R172.1 R182.2 U19.13(Strap7/RX_D3) ; port MII.RXD3
TD_N: J4.5(TD-) U19.6(TD_M) U27.4(D2+) U27.7(NC)
TD_P: J4.3(TD+) U19.7(TD_P) U27.5(D2-) U27.6(NC)
NetC128_2: C128.2 U19.2(CEXT)
NetC129_1: C129.1 C130.1 C131.2 C135.2 L7.1 U19.3(VDDA3V3)
NetC132_1: C132.1 C133.1 C134.2 C137.2 L8.1 U19.17(VDDIO)
NetC136_1: C136.1 C139.2 J4.4(CTD)
NetC138_1: C138.1 C141.2 J4.7(CRD)
NetC168_2: C168.2 R164.1 U19.32(~{RST}) U26.4(Y)
NetJ4_2: J4.2 R192.2
NetJ4_10: J4.10 R191.2
NetR163_2: R163.2 U19.10(RBIAS)
NetR189_1: R189.1 U19.1(ModeSelect)
NetR190_1: R190.1 U19.21(PWRDN/INT)
NetU19_11: U19.11(MDIO) ; port MDIO.MDIO
NetU19_12: U19.12(MDC) ; port MDIO.MDC
NetU19_14: U19.14(Strap8/RX_D2) ; port MII.RXD2
NetU19_15: U19.15(Strap9/RX_D1) ; port MII.RXD1
NetU19_16: U19.16(Strap0/RX_D0) ; port MII.RXD0
NetU19_18: U19.18(RX_DV/CRS_DV/Strap10) ; port MII.RXDV
NetU19_19: U19.19(RX_CLK/50MHz_RMII/Strap11) ; port MII.RXCLK
NetU19_22: U19.22(TX_CLK/Strap5) ; port MII.TXCLK
NetU19_23: U19.23(TX_EN) ; port MII.TXEN
NetU19_24: U19.24(TX_D0) ; port MII.TXD0
NetU19_25: U19.25(TX_D1) ; port MII.TXD1
NetU19_26: U19.26(TX_D2) ; port MII.TXD2
NetU19_27: U19.27(TX_D3) ; port MII.TXD3
NetU26_2: U26.2(B) ; port MII.RESET

Not connected (* = marked no-connect by the designer): U19 8(XO)* 28(COL/LED2/TX_ER/GPIO/Strap4)

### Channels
Eth1: designators end in .1; ports 25MHz=25MHz ~{WARMRST}=~{WARMRST}
Eth2: designators end in .2; ports 25MHz=25MHz ~{WARMRST}=~{WARMRST}

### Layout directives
differential pair; differential pair class D100: RD_N_Eth1, RD_P_Eth1, TD_N_Eth1, TD_P_Eth1
net class MII_TX: (no net found under the mark)
net class MII_RX: Strap6, Strap7

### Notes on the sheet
- Odd nibble detection disbaled
  MII MAC
  Fast Link Drop
  auto MDIX
  MDIO 1 and 3

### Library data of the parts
C127 = CMP-0006473-2: CAP, CERM, 4.7 pF, 50 V, +/- 1%, C0G/NP0, 0402; Manufacturer: MuRata; TaMin_C: -55°C; Polarized: N; SizeAreaWB_mm2: 3; Value1: Unknown; U/M: EA; Value: 4.7pF; TaMax_C: 125°C; SizeZ_mm: 0.6; SizeX_mm: 1; SizeY_mm: 0.5; AEC Category: Q200
C128 = CMP-0119293-1: WCAP-CSGP Multilayer Ceramic Chip Capacitor, General Purpose, size 0402, X7R, 2.2nF, 50VDC; Manufacturer: Wurth Elektronik; Capacitance Tolerance: +/-10%; Case/Size Code: 0402; Dissipation Factor: 2.5%; Insulation Resistance: 10GOhm; Rated Voltage (DC): 50V; Technical Reference: X7R0402222K050DFCT10000
C129 C132 = CMP-0750070-1: as C110 on sheet Power
C130 C133 C136 C138 = CMP-0064924-2: CAP, CERM, 1 uF, 10 V,+/- 20%, X5R, 0402; Manufacturer: Wurth Elektronik; TaMin_C: -55°C; Polarized: N; SizeAreaWB_mm2: 3; Value1: Unknown; U/M: EA; Value: 1uF; TaMax_C: 85°C; SizeZ_mm: 0.6; SizeX_mm: 1; SizeY_mm: 0.5; Cap_F: 1µF; AEC Category: Q200
C131 C134 C168 C169 = CMP-0119242-1: WCAP-CSGP Multilayer Ceramic Chip Capacitor, General Purpose, size 0402, X7R, 10nF, 10VDC; Manufacturer: Wurth Elektronik; Capacitance Tolerance: +/-10%; Case/Size Code: 0402; Dissipation Factor: 5%; Insulation Resistance: 10GOhm; Technical Reference: X7R0402103K010DFCT10000
C135 C137 C139 C141 C142 = CMP-0119143-1: as C103 on sheet Power
C140 = CMP-0009301-2: CAP, CERM, 0.01 uF, 2000 V, +/- 10%, X7R, 1825; Manufacturer: AVX; TaMin_C: -55°C; Polarized: N; SizeAreaWB_mm2: 54.6; Value1: Unknown; U/M: EA; Value: 0.01uF; TaMax_C: 125°C; SizeZ_mm: 1.1; SizeX_mm: 4.5; SizeY_mm: 6.4; Value2: 2000V; SizeArea_mm2: 28.8; Cap_F: 10nF; AEC Category: Q200
D26 D27 = CMP-0120655-1: 1-pF, 5.5-V, 30-KV ESD protection device in 0201 package 2-X2SON -40 to 125; Manufacturer: Texas Instruments; SizeZ_mm: 0.32mm; AEC Qualified: No; Breakdown Voltage: 6V; Cap_F: 1pF; Clamping Voltage: 3.8V; Direction: Unidirectional; Ipp: 6A; Number Of Channels: 1; Ppk: 45W; Standoff Height: 0mm; TaMax_C: +150°C; TaMin_C: -55°C; VRWM: 5.5V
J4 = 7498011211: WE-RJ45 LAN Transformer, SMT, 10/100 Base-T, Tab Down, 1 Port; Manufacturer: Wurth Elektronik; LED: green-yellow; Number of Ports: 1; PoE: non-PoE; Shield Tabs: Yes; USB: No USB
L7 L8 = CMP-0003233-1: Ferrite Bead, 600 ohm @ 100 MHz, 0.3 A, 0402; Manufacturer: Wurth Elektronik; Ztyp@1GHz_Ohm: 385.838; ZTyp@100MHz_Ohm: 600; SizeAreaWB_mm2: 3; DCR_ohm: 0.6; Value1: 0.6 ohm; Value: 600 ohm; Imax_A: 300mA; SizeX_mm: 1; SizeY_mm: 0.5; Value2: 0.3A
R163 = CMP-0026515-2: RES, 6.49 k, 1%, 0.063 W, AEC-Q200 Grade 0, 0402; Manufacturer: Vishay-Dale; Power_W: 63mW; TempCo: 100 ppm/C; Value_Code: 6k49; Value: 6.49k; EIA_Code: E96; SizeX_mm: 1; SizeY_mm: 0.5; SizeZ_mm: 0.6; Value2: 0.063W; AEC Qualified: Y; VDC_V: 50V; AEC Category: Q200; AEC Grade: 0
R164 R189 R190 = CMP-0026825-5: as R141 on sheet Power
R166-R168 R171 R172 = CMP-0026237-2: RES, 2.49 k, 1%, 0.063 W, AEC-Q200 Grade 0, 0402; Manufacturer: Vishay-Dale; Power_W: 63mW; TempCo: 100 ppm/C; Value_Code: 2k49; Value: 2.49k; EIA_Code: E96; SizeX_mm: 1; SizeY_mm: 0.5; SizeZ_mm: 0.6; Value2: 0.063W; AEC Qualified: Y; VDC_V: 50V; AEC Category: Q200; AEC Grade: 0
R176-R178 R181 R182 = CMP-0026088-3: RES, 1.50 k, 1%, 0.063 W, AEC-Q200 Grade 0, 0402; Manufacturer: Vishay-Dale; Power_W: 63mW; TempCo: 100 ppm/C; Value_Code: 1k50; Value: 1.50k; EIA_Code: E96; Res_ohm: 1.5k; SizeX_mm: 1; SizeY_mm: 0.5; SizeZ_mm: 0.6; Value2: 0.063W; AEC Qualified: Y; VDC_V: 50V; AEC Category: Q200; AEC Grade: 0
R191 R192 = CMP-0025756-4: RES, 220, 5%, 0.1 W, AEC-Q200 Grade 0, 0603; Manufacturer: Vishay-Dale; Power_W: 100mW; TempCo: 200 ppm/C; Value_Code: 220R; Value: 220; EIA_Code: E24; SizeX_mm: 1.6; SizeY_mm: 0.8; SizeZ_mm: 1; Value2: 0.1W; SizeArea_mm2: 1.28; AEC Qualified: Y; VDC_V: 75V; AEC Category: Q200; AEC Grade: 0
R193 = CMP-0016081-3: RES, 1.0 M, 5%, 0.75 W, AEC-Q200 Grade 0, 2010; Manufacturer: Vishay-Dale; TempCo: 200 ppm/C; Value_Code: 1M00; Value: 1.0Meg; EIA_Code: E24; Res_ohm: 1M; SizeX_mm: 5; SizeY_mm: 2.5; SizeZ_mm: 1.66; Value2: 0.75W; SizeArea_mm2: 12.5; AEC Qualified: Y; VDC_V: 400V; AEC Grade: 0; AEC Category: Q200
U19 = CMP-0124715-2: Deterministic, Low-Latency, Low-Power, 10/100 Mbps, Industrial Ethernet PHY; Manufacturer: Texas Instruments; SizeZ_mm: 1mm; AEC Qualified: No; Data Rate: 100Mbits/s; Interface: Ethernet,Other; Max Supply Voltage: 3.6V; Min Supply Voltage: 1.62V; Number Of Channels: 1; Simplex Duplex: Full-Duplex; Standoff Height: 0mm; TaMax_C: +85°C; TaMin_C: -40°C; AEC Category: Q200; CompType: IC
U26 = CMP-0051264-2: Single 2-Input Positive–AND Gate with Open Drain Output,  DBV0005A (SOT-23-5); Manufacturer: Texas Instruments; 3-State Output: No; Input Type: CMOS; Bits(#): 1; F @ Nom Voltage(Max)(Mhz): 75; tpd @ Nom Voltage(Max)(ns): 11,7.5; Voltage(Nom)(V): 3.3,5; Output Drive (IOL/IOH)(Max)(mA): 50/-50; Gate Type: AND; VCC(Max)(V): 5.5; ICC @ Nom Voltage(Max)(mA): 0.01; VCC(Min)(V): 2; Logic: True; Rating: Catalog; AEC Category: Q200; AEC Qualified: N; CompType: IC; SizeAreaWB_mm2: 14.82; SizeArea_mm2: 8.12; SizeX_mm: 2.8; SizeY_mm: 2.9; SizeZ_mm: 1.45
U27 = CMP-0079927-2: ESD204, DQA0010A (USON-10); Alternate PartNumber: ESD204DQAT; Alternate Manufacturer: Texas Instruments; SizeAreaWB_mm2: 7; SizeZ_mm: 0.55; SizeX_mm: 1; SizeY_mm: 2.5; CompType: IC; AEC Qualified: N; AEC Category: Q200

## Sheet RemoteIO_CPU_IO.SchDoc
size 431 x 279 mm; Date: Not shown in title block; ApprovedBy: Not shown in title block; CheckedBy: Not shown in title block; Author: Not shown in title block; CompanyName: Not shown in title block; Engineer: Not shown in title block; Organization: Not shown in title block; Address1: Not shown in title block; Address2: Not shown in title block; Address3: Not shown in title block; Address4: Not shown in title block; DocumentNumber: 5; Revision: Use project parameter SCH_Rev; SheetNumber: 5; SheetTotal: 14; PageSetup: Record=PageOptions¦CenterHorizontal=True¦CenterVertical=True¦PrintScale=1.00¦XCorrection=1.00¦YCorrection=1.00¦PrintKind=0¦BorderSize=5000000¦LeftOffset=0¦BottomOffset=0¦Orientation=2¦PaperLength=1000¦PaperWidth=1000¦Scale=100¦PaperSource=15¦PrintQuality=600¦MediaType=1¦DitherType=10¦PaperKind=Letter¦PrintScaleMode=1
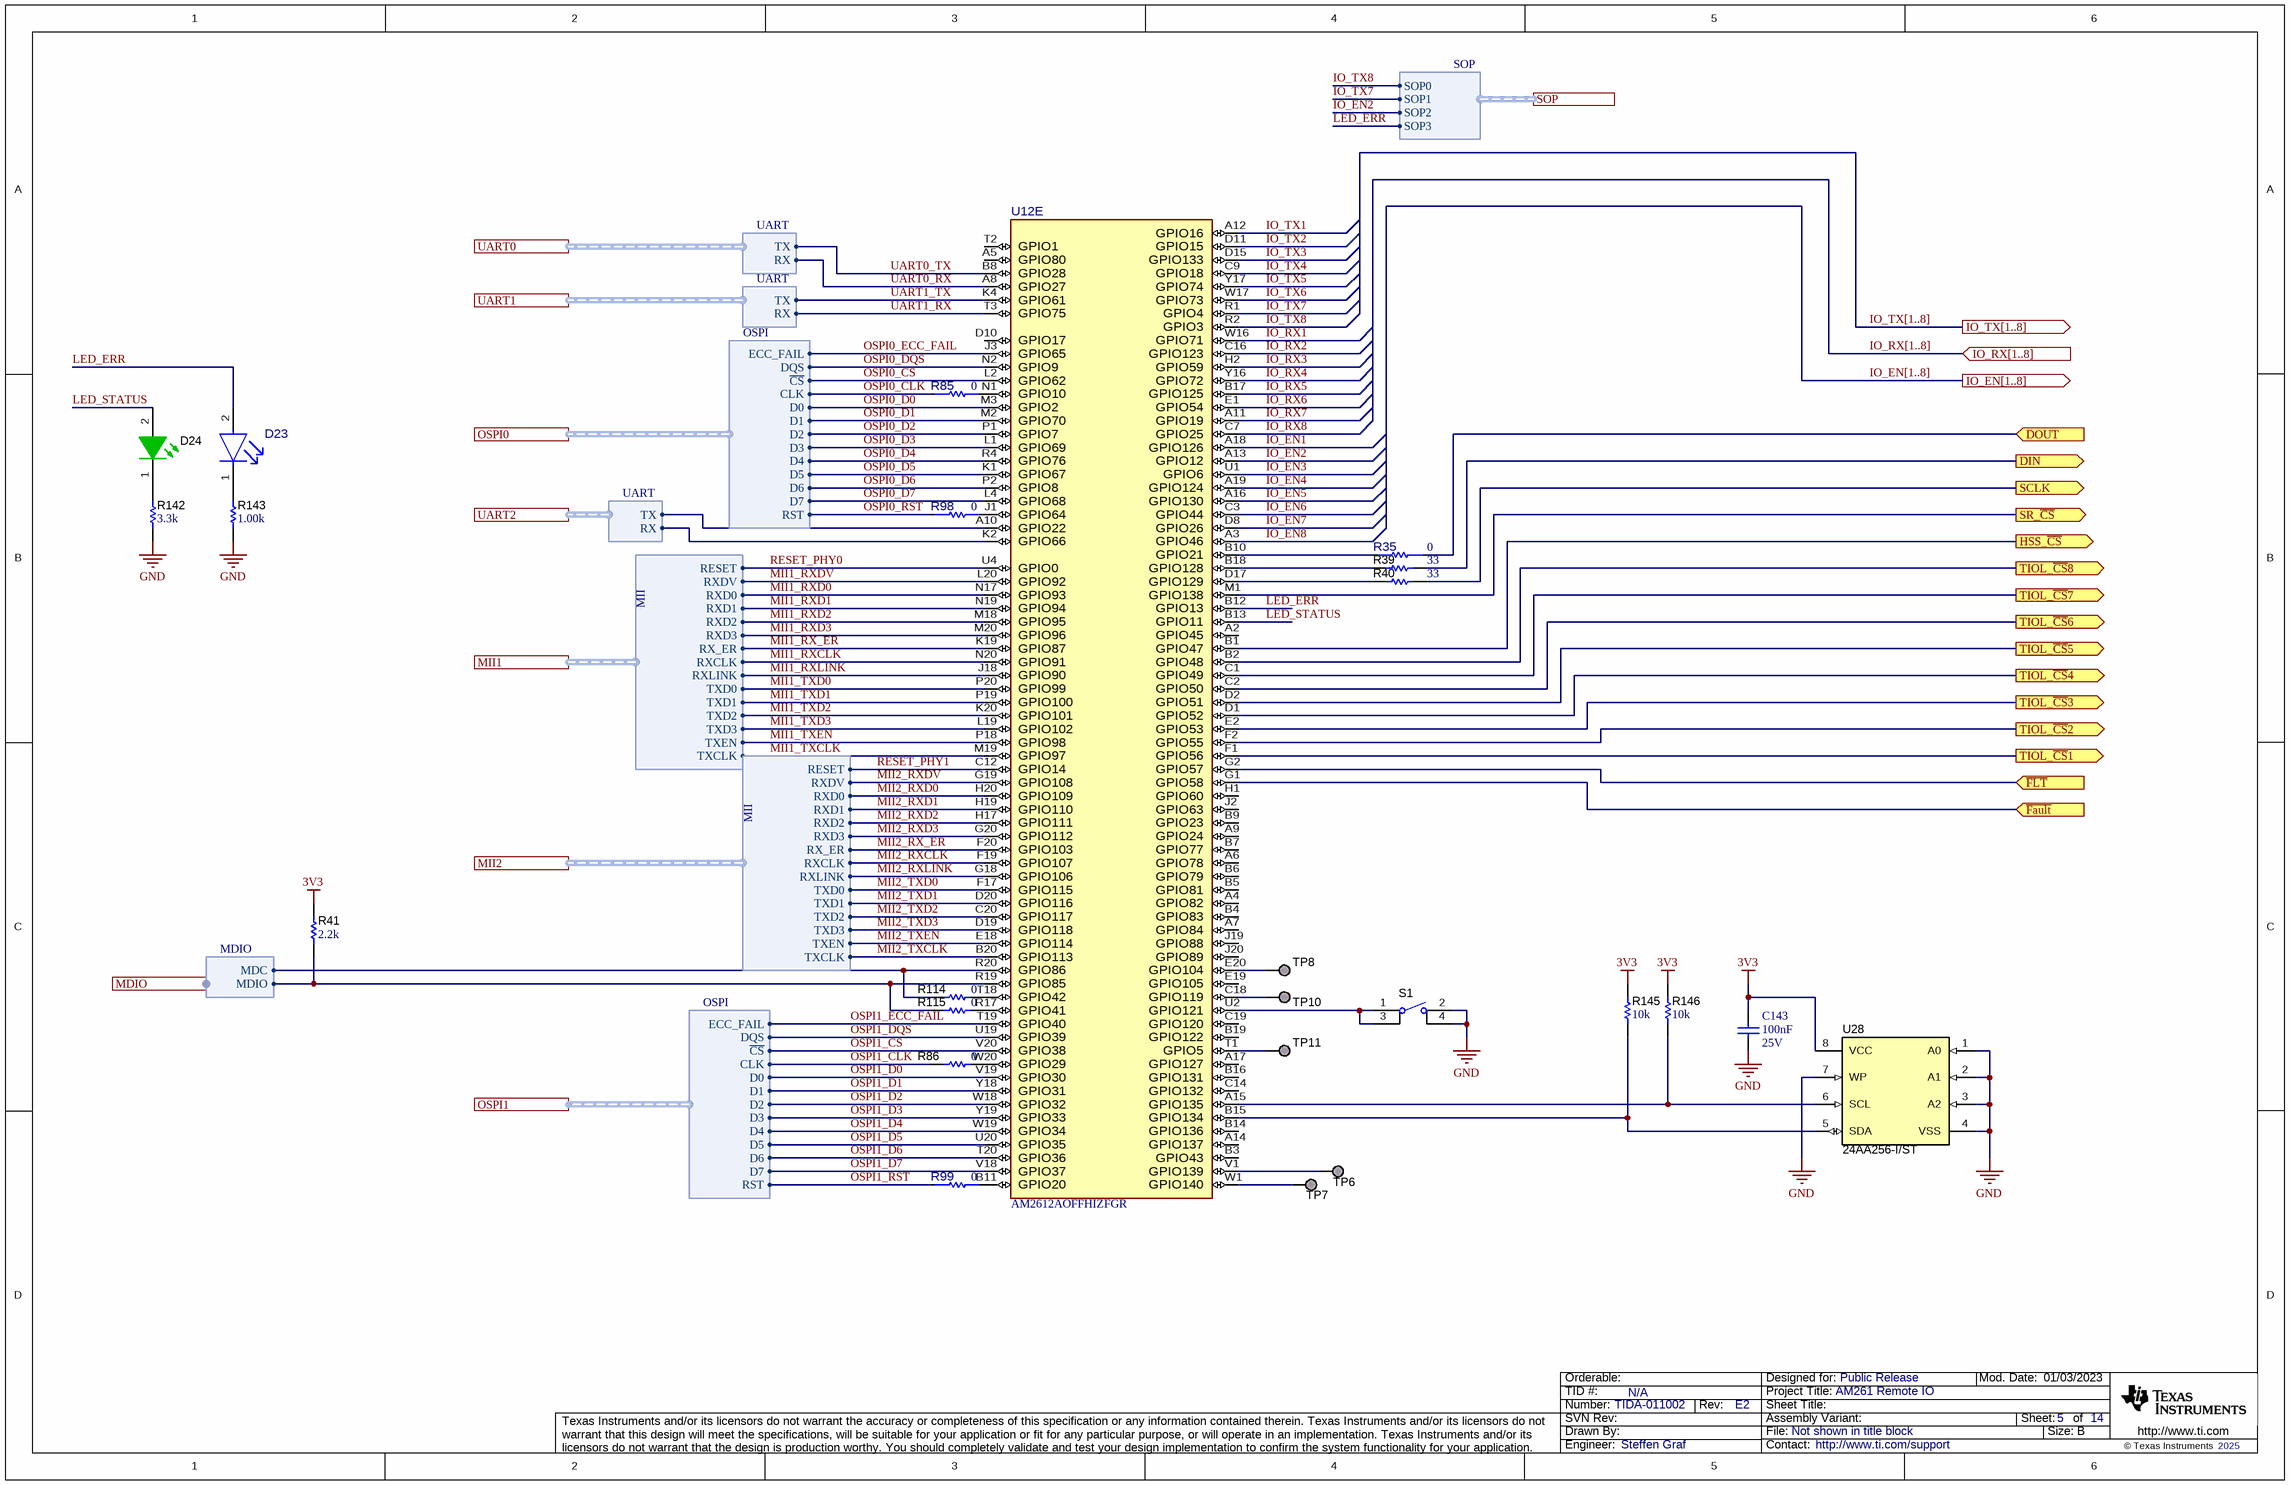
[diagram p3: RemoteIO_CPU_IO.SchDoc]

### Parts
C143  Cap_F: 100nF  Rated Voltage (DC): 25V  [WCAP-CSGP_0402_L1W0.5H0.5]  (hidden comment: 885012105018)
D23  150040RS73240  [FP-150040RS73220_0402-MFG]  (value not drawn)
D24  150040GS73240  [WL-SMCC_0402_Green]  (value not drawn)
R35  value 0  [FP-CRCW04020000Z0EDC_0402-MFG]  (hidden comment: CRCW04020000Z0EDC)
R39  ValueDisplayed: 33  [0402]  (hidden comment: CRCW040233R0JNED)
R40  ValueDisplayed: 33  [0402]  (hidden comment: CRCW040233R0JNED)
R41  ValueDisplayed: 2.2k  [0402]  (hidden comment: CRCW04022K20JNED)
R85  value 0  [FP-CRCW04020000Z0EDC_0402-MFG]  (hidden comment: CRCW04020000Z0EDC)
R86  ValueDisplayed: 0  [0201L]  (hidden comment: CRCW02010000Z0ED)
R98  value 0  [FP-CRCW04020000Z0EDC_0402-MFG]  (hidden comment: CRCW04020000Z0EDC)
R99  value 0  [FP-CRCW04020000Z0EDC_0402-MFG]  (hidden comment: CRCW04020000Z0EDC)
R114  ValueDisplayed: 0  [0201L]  (hidden comment: CRCW02010000Z0ED)
R115  ValueDisplayed: 0  [0201L]  (hidden comment: CRCW02010000Z0ED)
R142  ValueDisplayed: 3.3k  [0402]  (hidden comment: CRCW04023K30JNED)
R143  ValueDisplayed: 1.00k  [0402]  (hidden comment: CRCW04021K00FKED)
R145  ValueDisplayed: 10k  [0402]  (hidden comment: CRCW040210K0JNED)
R146  ValueDisplayed: 10k  [0402]  (hidden comment: CRCW040210K0JNED)
S1  434153017835  [SW_434153017835]  (value not drawn)
TP6  TESTPOINT  [TP_25MIL-SMT]  (value not drawn)  (no BOM)
TP7  TESTPOINT  [TP_25MIL-SMT]  (value not drawn)  (no BOM)
TP8  TESTPOINT  [TP_25MIL-SMT]  (value not drawn)  (no BOM)
TP10  TESTPOINT  [TP_25MIL-SMT]  (value not drawn)  (no BOM)
TP11  TESTPOINT  [TP_25MIL-SMT]  (value not drawn)  (no BOM)
U12  AM2612AOFFHIZFGR  [ZFG0304A-MFG]  (part E of 7)
U28  24AA256-I/ST  [TSSOP-8]

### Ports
DIN (out), DOUT (in), HSS_~{CS} (out), IO_EN[1..8] (out), IO_RX[1..8] (in), IO_TX[1..8] (out), MDIO (harness MDIO), MII1 (harness MII), MII2 (harness MII), OSPI0 (harness OSPI), OSPI1 (harness OSPI), SCLK (out), SOP (harness SOP), SR_~{CS} (out), TIOL_~{CS}1 (out), TIOL_~{CS}2 (out), TIOL_~{CS}3 (out), TIOL_~{CS}4 (out), TIOL_~{CS}5 (out), TIOL_~{CS}6 (out), TIOL_~{CS}7 (out), TIOL_~{CS}8 (out), UART0 (harness UART), UART1 (harness UART), UART2 (harness UART), ~{Fault} (in), ~{FLT} (in)

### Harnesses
MII: RXDV, RXD0, RXD1, RXD2, RXD3, RX_ER, RXCLK, RXLINK, TXD0, TXD1, TXD2, TXD3, TXEN, TXCLK, RESET
MDIO: MDC, MDIO
UART: TX, RX
OSPI: ~{CS}, CLK, D0, D1, D2, D3, D4, D5, D6, D7, DQS, ECC_FAIL, RST
SOP: SOP0, SOP1, SOP2, SOP3

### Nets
3V3: C143.2 R41.1 R145.1 R146.1 U28.8(VCC)
GND: C143.1 R142.1 R143.1 S1.2 S1.4 U28.1(A0) U28.2(A1) U28.3(A2) U28.4(VSS) U28.7(WP)
~{Fault}: U12.G1(GPIO58) ; port ~{Fault}
~{FLT}: U12.G2(GPIO57) ; port ~{FLT}
CS1: U12.F1(GPIO56) ; port TIOL_~{CS}1
CS2: U12.F2(GPIO55) ; port TIOL_~{CS}2
CS3: U12.E2(GPIO53) ; port TIOL_~{CS}3
CS4: U12.D1(GPIO52) ; port TIOL_~{CS}4
CS5: U12.D2(GPIO51) ; port TIOL_~{CS}5
CS6: U12.C2(GPIO50) ; port TIOL_~{CS}6
CS7: U12.C1(GPIO49) ; port TIOL_~{CS}7
CS8: U12.B2(GPIO48) ; port TIOL_~{CS}8
DIN: R39.2 ; port DIN
DOUT: R35.1 ; port DOUT
HSS_~{CS}: U12.B1(GPIO47) ; port HSS_~{CS}
IO_EN1: U12.A18(GPIO126)
IO_EN2: U12.A13(GPIO12) ; port SOP.SOP2
IO_EN3: U12.U1(GPIO6)
IO_EN4: U12.A19(GPIO124)
IO_EN5: U12.A16(GPIO130)
IO_EN6: U12.C3(GPIO44)
IO_EN7: U12.D8(GPIO26)
IO_EN8: U12.A3(GPIO46)
IO_RX1: U12.W16(GPIO71)
IO_RX2: U12.C16(GPIO123)
IO_RX3: U12.H2(GPIO59)
IO_RX4: U12.Y16(GPIO72)
IO_RX5: U12.B17(GPIO125)
IO_RX6: U12.E1(GPIO54)
IO_RX7: U12.A11(GPIO19)
IO_RX8: U12.C7(GPIO25)
IO_TX1: U12.A12(GPIO16)
IO_TX2: U12.D11(GPIO15)
IO_TX3: U12.D15(GPIO133)
IO_TX4: U12.C9(GPIO18)
IO_TX5: U12.Y17(GPIO74)
IO_TX6: U12.W17(GPIO73)
IO_TX7: U12.R1(GPIO4) ; port SOP.SOP1
IO_TX8: U12.R2(GPIO3) ; port SOP.SOP0
LED_ERR: D23.2(ANODE) U12.B12(GPIO13) ; port SOP.SOP3
LED_STATUS: D24.2(A) U12.B13(GPIO11)
MII1_RX_ER: U12.K19(GPIO87) ; port MII1.RX_ER
MII1_RXCLK: U12.N20(GPIO91) ; port MII1.RXCLK
MII1_RXD0: U12.N17(GPIO93) ; port MII1.RXD0
MII1_RXD1: U12.N19(GPIO94) ; port MII1.RXD1
MII1_RXD2: U12.M18(GPIO95) ; port MII1.RXD2
MII1_RXD3: U12.M20(GPIO96) ; port MII1.RXD3
MII1_RXDV: U12.L20(GPIO92) ; port MII1.RXDV
MII1_RXLINK: U12.J18(GPIO90) ; port MII1.RXLINK  [project net LED_Link]
MII1_TXCLK: U12.M19(GPIO97) ; port MII1.TXCLK
MII1_TXD0: U12.P20(GPIO99) ; port MII1.TXD0
MII1_TXD1: U12.P19(GPIO100) ; port MII1.TXD1
MII1_TXD2: U12.K20(GPIO101) ; port MII1.TXD2
MII1_TXD3: U12.L19(GPIO102) ; port MII1.TXD3
MII1_TXEN: U12.P18(GPIO98) ; port MII1.TXEN
MII2_RX_ER: U12.F20(GPIO103) ; port MII2.RX_ER
MII2_RXCLK: U12.F19(GPIO107) ; port MII2.RXCLK
MII2_RXD0: U12.H20(GPIO109) ; port MII2.RXD0
MII2_RXD1: U12.H19(GPIO110) ; port MII2.RXD1
MII2_RXD2: U12.H17(GPIO111) ; port MII2.RXD2
MII2_RXD3: U12.G20(GPIO112) ; port MII2.RXD3
MII2_RXDV: U12.G19(GPIO108) ; port MII2.RXDV
MII2_RXLINK: U12.G18(GPIO106) ; port MII2.RXLINK  [project net LED_Link]
MII2_TXCLK: U12.B20(GPIO113) ; port MII2.TXCLK
MII2_TXD0: U12.F17(GPIO115) ; port MII2.TXD0
MII2_TXD1: U12.D20(GPIO116) ; port MII2.TXD1
MII2_TXD2: U12.C20(GPIO117) ; port MII2.TXD2
MII2_TXD3: U12.D19(GPIO118) ; port MII2.TXD3
MII2_TXEN: U12.E18(GPIO114) ; port MII2.TXEN
OSPI0_~{CS}: U12.L2(GPIO62) ; port OSPI0.~{CS}
OSPI0_CLK: R85.1 ; port OSPI0.CLK
OSPI0_D0: U12.M3(GPIO2) ; port OSPI0.D0
OSPI0_D1: U12.M2(GPIO70) ; port OSPI0.D1
OSPI0_D2: U12.P1(GPIO7) ; port OSPI0.D2
OSPI0_D3: U12.L1(GPIO69) ; port OSPI0.D3
OSPI0_D4: U12.R4(GPIO76) ; port OSPI0.D4
OSPI0_D5: U12.K1(GPIO67) ; port OSPI0.D5
OSPI0_D6: U12.P2(GPIO8) ; port OSPI0.D6
OSPI0_D7: U12.L4(GPIO68) ; port OSPI0.D7
OSPI0_DQS: U12.N2(GPIO9) ; port OSPI0.DQS
OSPI0_ECC_FAIL: U12.J3(GPIO65) ; port OSPI0.ECC_FAIL
OSPI0_RST: R98.1 ; port OSPI0.RST
OSPI1_~{CS}: U12.V20(GPIO38) ; port OSPI1.~{CS}
OSPI1_CLK: R86.1 ; port OSPI1.CLK
OSPI1_D0: U12.V19(GPIO30) ; port OSPI1.D0
OSPI1_D1: U12.Y18(GPIO31) ; port OSPI1.D1
OSPI1_D2: U12.W18(GPIO32) ; port OSPI1.D2
OSPI1_D3: U12.Y19(GPIO33) ; port OSPI1.D3
OSPI1_D4: U12.W19(GPIO34) ; port OSPI1.D4
OSPI1_D5: U12.U20(GPIO35) ; port OSPI1.D5
OSPI1_D6: U12.T20(GPIO36) ; port OSPI1.D6
OSPI1_D7: U12.V18(GPIO37) ; port OSPI1.D7
OSPI1_DQS: U12.U19(GPIO39) ; port OSPI1.DQS
OSPI1_ECC_FAIL: U12.T19(GPIO40) ; port OSPI1.ECC_FAIL
OSPI1_RST: R99.1 ; port OSPI1.RST
RESET_PHY0: U12.U4(GPIO0) ; port MII1.RESET
RESET_PHY1: U12.C12(GPIO14) ; port MII2.RESET
SCLK: R40.2 ; port SCLK
SR_~{CS}: U12.M1(GPIO138) ; port SR_~{CS}
UART0_RX: U12.A8(GPIO27) ; port UART0.RX
UART0_TX: U12.B8(GPIO28) ; port UART0.TX
UART1_RX: U12.T3(GPIO75) ; port UART1.RX
UART1_TX: U12.K4(GPIO61) ; port UART1.TX
NetD23_1: D23.1(CATHODE) R143.2
NetD24_1: D24.1(K) R142.2
NetJ9_2: U12.K2(GPIO66) ; port UART2.RX
NetJ9_3: U12.A10(GPIO22) ; port UART2.TX
NetR35_2: R35.2 U12.B10(GPIO21)
NetR39_1: R39.1 U12.B18(GPIO128)
NetR40_1: R40.1 U12.D17(GPIO129)
NetR41_2: R41.2 R115.1 U12.R19(GPIO85) ; port MDIO.MDIO
NetR85_2: R85.2 U12.N1(GPIO10)
NetR86_2: R86.2 U12.W20(GPIO29)
NetR98_2: R98.2 U12.J1(GPIO64)
NetR99_2: R99.2 U12.B11(GPIO20)
NetR114_1: R114.1 U12.R20(GPIO86) ; port MDIO.MDC
NetR114_2: R114.2 U12.T18(GPIO42)
NetR115_2: R115.2 U12.R17(GPIO41)
NetR145_2: R145.2 U12.B15(GPIO134) U28.5(SDA)
NetR146_2: R146.2 U12.A15(GPIO135) U28.6(SCL)
NetS1_1: S1.1 S1.3 U12.U2(GPIO121)
NetTP6_1: TP6.1 U12.V1(GPIO139)
NetTP7_1: TP7.1 U12.W1(GPIO140)
NetTP8_1: TP8.1 U12.E20(GPIO104)
NetTP10_1: TP10.1 U12.C18(GPIO119)
NetTP11_1: TP11.1 U12.T1(GPIO5)

Not connected (* = marked no-connect by the designer): U12 A2(GPIO45) A4(GPIO82) A5(GPIO80) A6(GPIO78) A7(GPIO84) A9(GPIO24) A14(GPIO137) A17(GPIO127) B3(GPIO43) B4(GPIO83) B5(GPIO81) B6(GPIO79) B7(GPIO77) B9(GPIO23) B14(GPIO136) B16(GPIO131) B19(GPIO122) C14(GPIO132) C19(GPIO120) D10(GPIO17) E19(GPIO105) H1(GPIO60) J2(GPIO63) J19(GPIO88) J20(GPIO89) T2(GPIO1)

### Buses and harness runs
bus IO_EN[1..8] = port IO_EN[1..8]
bus IO_RX[1..8] = port IO_RX[1..8]
bus IO_TX[1..8] = port IO_TX[1..8]

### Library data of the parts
C143 = CMP-0119143-1: as C103 on sheet Power
D23 = CMP-0122246-1: Red 624nm LED Indication - Discrete 2V 0402 (1005 Metric); Manufacturer: Wurth; Angle: 120°; LambdaP: 632nm; Power_TotalModule: 48mW; SizeZ_mm: 0.35mm; Tjmax_C: 115°C; Vr_V: 5V; AEC Qualified: No; Forward Current: 20mA; Led Orientation: Top View; Luminous Intensity: 110mcd
D24 = CMP-0081765-2: as D20 on sheet Power
R35 R85 R98 R99 = CMP-0093210-1: as R117 on sheet Power
R39 R40 = CMP-0026908-3: RES, 33, 5%, 0.063 W, AEC-Q200 Grade 0, 0402; Manufacturer: Vishay-Dale; Power_W: 63mW; TempCo: 200 ppm/C; Value_Code: 33R0; Value: 33; EIA_Code: E24; SizeX_mm: 1; SizeY_mm: 0.5; SizeZ_mm: 0.6; Value2: 0.063W; AEC Qualified: Y; VDC_V: 50V; AEC Category: Q200; AEC Grade: 0
R41 = CMP-0026890-5: RES, 2.2 k, 5%, 0.063 W, AEC-Q200 Grade 0, 0402; Manufacturer: Vishay-Dale; Power_W: 63mW; TempCo: 200 ppm/C; Value_Code: 2k20; Value: 2.2k; EIA_Code: E24; SizeX_mm: 1; SizeY_mm: 0.5; SizeZ_mm: 0.6; Value2: 0.063W; AEC Qualified: Y; VDC_V: 50V; AEC Category: Q200; AEC Grade: 0
R86 R114 R115 = CMP-0027008-4: RES, 0, 5%, 0.05 W, 0201; Manufacturer: Vishay-Dale; Power_W: 50mW; TempCo: ppm/C; Value_Code: 0000; Value: 0; EIA_Code: E24; SizeX_mm: 0.6; SizeY_mm: 0.3; SizeZ_mm: 0.26; Value2: 0.05W; SizeArea_mm2: 0.18; AEC Qualified: N; AEC Category: Q200
R142 = CMP-0026918-5: as R138 on sheet Power
R143 = CMP-0026071-3: as R123 on sheet Power
R145 R146 = CMP-0026825-5: as R141 on sheet Power
S1 = CMP-0002302-1: Switch, SPST, Off-Mom, 0.05 A, 12 VDC, SMD; Manufacturer: Wurth Elektronik; CurrentRating_mA: 50A; PositionCount: 1; SizeX_mm: 4.3; SizeY_mm: 2.9; SizeZ_mm: 1.9; SizeArea_mm2: 12.47; VDC_V: 12V; SizeAreaWB_mm2: 20.67
TP6-TP8 TP10 TP11 = CMP-0078143-4: TEST POINT.  No entry in BOM.
U12 = CMP-0126016-1: ARM® Cortex®-R5F Sitara™ Microcontroller IC 32-Bit Dual-Core 500MHz 512KB (512K x 8) Tightly Coupled Memory (TCM) 304-NFBGA (13.25x13.25); Manufacturer: Texas Instruments; SizeZ_mm: 1.3mm; AEC Qualified: No; Core Architecture: ARM Cortex-R5F; Data Bus Width: 32bits; Interface: I2C,SPI,UART,CAN,USB,LIN,Ethernet; Max Supply Voltage: 3.465V; Min Supply Voltage: 1.14V; Number Of A/D Converters: 3; Number Of Adc Channels: 7; Number Of Cores: 2; Number Of Ethernet Channels: 1; Number Of I/Os: 141; Number Of Pwm Channels: 10; Number Of Spi Channels: 4; Number Of Uart Channels: 6; Ram Size: 1.5MBytes; Standoff Height: 0.23mm; TJmax_C: +125°C
U28 = CMP-0005248-2: 256K I2C™ CMOS Serial EEPROM, TSSOP-8; Manufacturer: Microchip; SizeAreaWB_mm2: 42; SizeZ_mm: 1.2; SizeX_mm: 6.4; SizeY_mm: 3; SizeArea_mm2: 19.2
